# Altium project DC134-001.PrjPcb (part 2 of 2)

## Sheet DC134_USB.SchDoc
size 431 x 279 mm; Date: Not shown in title block; ApprovedBy: Not shown in title block; CheckedBy: Not shown in title block; Author: Not shown in title block; CompanyName: Not shown in title block; Engineer: Not shown in title block; Organization: Not shown in title block; Address1: Not shown in title block; Address2: Not shown in title block; Address3: Not shown in title block; Address4: Not shown in title block; DocumentNumber: 5; Revision: Use project parameter SCH_Rev; SheetNumber: 5; SheetTotal: 9; PageSetup: Record=PageOptions¦CenterHorizontal=True¦CenterVertical=True¦PrintScale=1.00¦XCorrection=1.00¦YCorrection=1.00¦PrintKind=0¦BorderSize=5000000¦LeftOffset=0¦BottomOffset=0¦Orientation=2¦PaperLength=1000¦PaperWidth=1000¦Scale=100¦PaperSource=15¦PrintQuality=600¦MediaType=1¦DitherType=10¦PaperKind=Letter¦PrintScaleMode=1
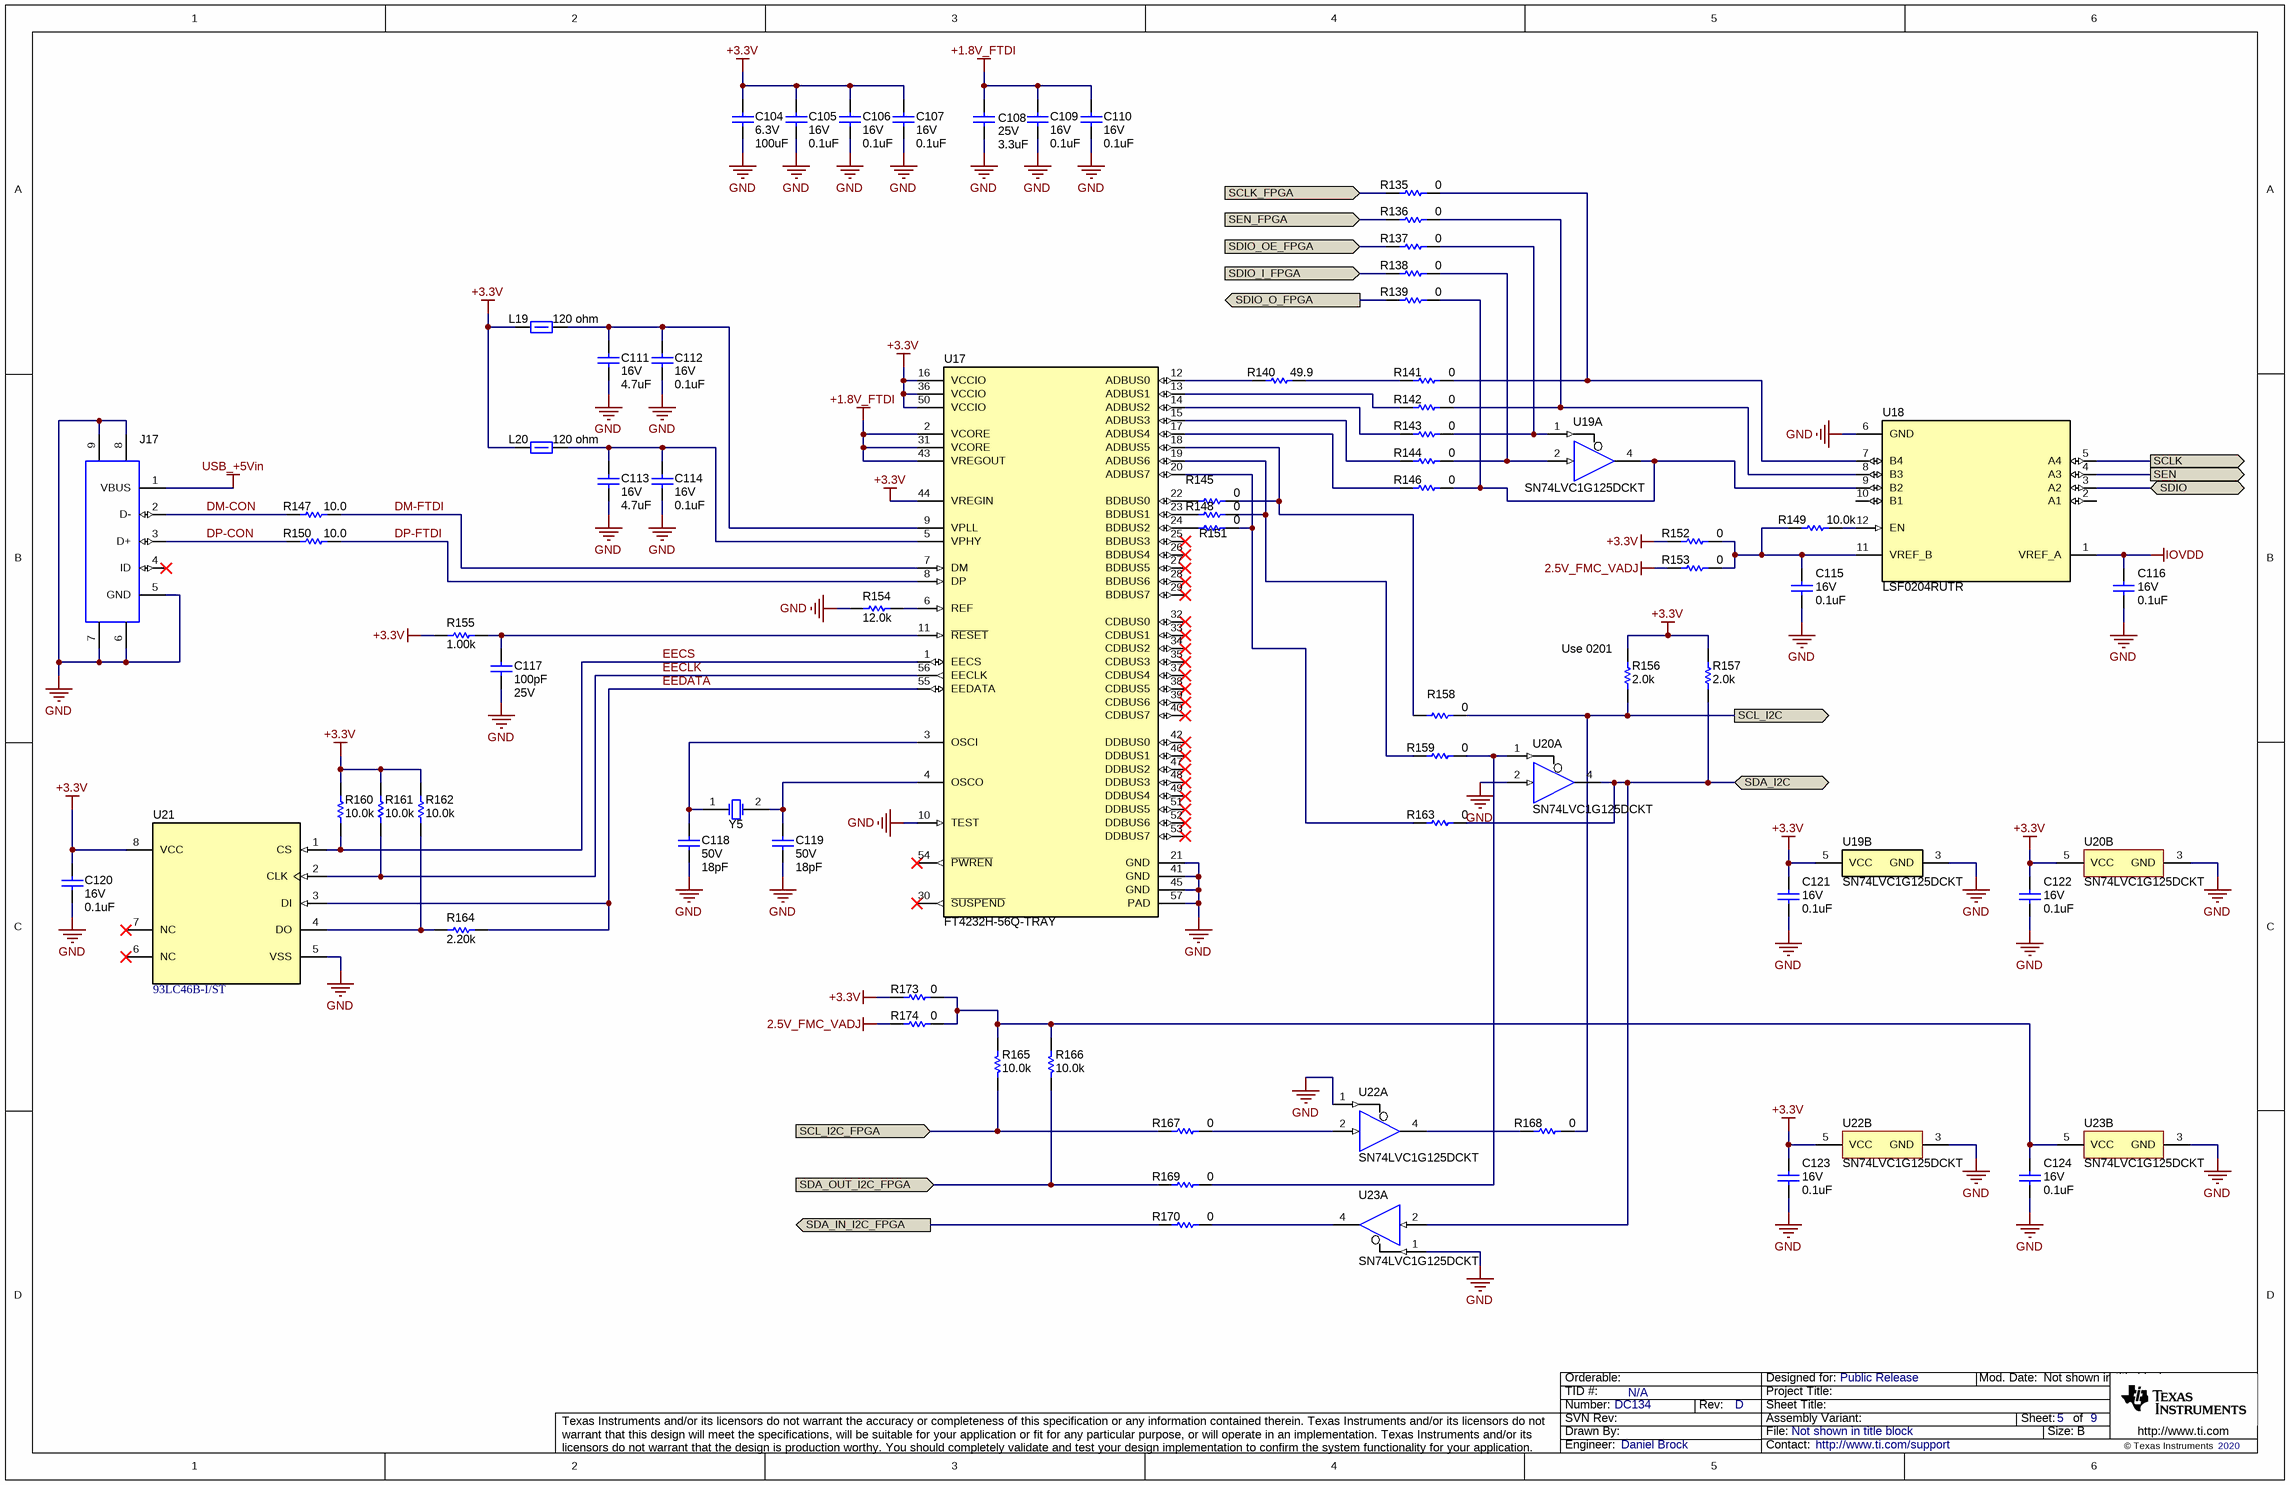
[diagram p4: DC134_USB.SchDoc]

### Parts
C104  VDC_V: 6.3V  ValueDisplayed: 100uF  [1206_190]  (hidden comment: C3216X5R0J107M160AB)
C105  VDC_V: 16V  ValueDisplayed: 0.1uF  [0201L]  (hidden comment: GRM033Z71C104KE14D)
C106  VDC_V: 16V  ValueDisplayed: 0.1uF  [0201L]  (hidden comment: GRM033Z71C104KE14D)
C107  VDC_V: 16V  ValueDisplayed: 0.1uF  [0201L]  (hidden comment: GRM033Z71C104KE14D)
C108  Value2: 25V  ValueDisplayed: 3.3uF  [0603]  (hidden comment: C1608X5R1E335K080AC)
C109  VDC_V: 16V  ValueDisplayed: 0.1uF  [0201L]  (hidden comment: GRM033Z71C104KE14D)
C110  VDC_V: 16V  ValueDisplayed: 0.1uF  [0201L]  (hidden comment: GRM033Z71C104KE14D)
C111  VDC_V: 16V  ValueDisplayed: 4.7uF  [0603]  (hidden comment: GRM188Z71C475KE21D)
C112  VDC_V: 16V  ValueDisplayed: 0.1uF  [0201L]  (hidden comment: GRM033Z71C104KE14D)
C113  VDC_V: 16V  ValueDisplayed: 4.7uF  [0603]  (hidden comment: GRM188Z71C475KE21D)
C114  VDC_V: 16V  ValueDisplayed: 0.1uF  [0201L]  (hidden comment: GRM033Z71C104KE14D)
C115  VDC_V: 16V  ValueDisplayed: 0.1uF  [0201L]  (hidden comment: GRM033Z71C104KE14D)
C116  VDC_V: 16V  ValueDisplayed: 0.1uF  [0201L]  (hidden comment: GRM033Z71C104KE14D)
C117  ValueDisplayed: 100pF  VDC_V: 25V  [0201L]  (hidden comment: CC0201JRNPO8BN101)
C118  VDC_V: 50V  ValueDisplayed: 18pF  [0402L]  (hidden comment: C1005C0G1H180J050BA)
C119  VDC_V: 50V  ValueDisplayed: 18pF  [0402L]  (hidden comment: C1005C0G1H180J050BA)
C120  VDC_V: 16V  ValueDisplayed: 0.1uF  [0201L]  (hidden comment: GRM033Z71C104KE14D)
C121  VDC_V: 16V  ValueDisplayed: 0.1uF  [0201L]  (hidden comment: GRM033Z71C104KE14D)
C122  VDC_V: 16V  ValueDisplayed: 0.1uF  [0201L]  (hidden comment: GRM033Z71C104KE14D)
C123  VDC_V: 16V  ValueDisplayed: 0.1uF  [0201L]  (hidden comment: GRM033Z71C104KE14D)
C124  VDC_V: 16V  ValueDisplayed: 0.1uF  [0201L]  (hidden comment: GRM033Z71C104KE14D)
J17  1734035-2  [CONN_USB-Mini-B-1734035-2]  (value not drawn)
L19  ValueDisplayed: 120 ohm  [0402]  (hidden comment: 74279271)
L20  ValueDisplayed: 120 ohm  [0402]  (hidden comment: 74279271)
R135  ValueDisplayed: 0  [0201L]  (hidden comment: CRCW02010000Z0ED)
R136  ValueDisplayed: 0  [0201L]  (hidden comment: CRCW02010000Z0ED)
R137  ValueDisplayed: 0  [0201L]  (hidden comment: CRCW02010000Z0ED)
R138  ValueDisplayed: 0  [0201L]  (hidden comment: CRCW02010000Z0ED)
R139  ValueDisplayed: 0  [0201L]  (hidden comment: CRCW02010000Z0ED)
R140  ValueDisplayed: 49.9  [0201L]  (hidden comment: RC0201FR-7D49R9L)
R141  ValueDisplayed: 0  [0201L]  (hidden comment: CRCW02010000Z0ED)
R142  ValueDisplayed: 0  [0201L]  (hidden comment: CRCW02010000Z0ED)
R143  ValueDisplayed: 0  [0201L]  (hidden comment: CRCW02010000Z0ED)
R144  ValueDisplayed: 0  [0201L]  (hidden comment: CRCW02010000Z0ED)
R145  ValueDisplayed: 0  [0201L]  (hidden comment: CRCW02010000Z0ED)
R146  ValueDisplayed: 0  [0201L]  (hidden comment: CRCW02010000Z0ED)
R147  ValueDisplayed: 10.0  [0402]  (hidden comment: RK73H1ETTP10R0F)
R148  ValueDisplayed: 0  [0201L]  (hidden comment: CRCW02010000Z0ED)
R149  ValueDisplayed: 10.0k  [0201L]  (hidden comment: RC0201FS-7D10KL)
R150  ValueDisplayed: 10.0  [0402]  (hidden comment: RK73H1ETTP10R0F)
R151  ValueDisplayed: 0  [0201L]  (hidden comment: CRCW02010000Z0ED)
R152  ValueDisplayed: 0  [0201L]  (hidden comment: CRCW02010000Z0ED)
R153  ValueDisplayed: 0  [0201L]  (hidden comment: CRCW02010000Z0ED)
R154  ValueDisplayed: 12.0k  [0201L]  (hidden comment: RC0201FR-7D12KL)
R155  ValueDisplayed: 1.00k  [0201L]  (hidden comment: RC0201FS-7D1KL)
R156  ValueDisplayed: 2.0k  [0402]  (hidden comment: CRCW04022K00JNED)
R157  ValueDisplayed: 2.0k  [0402]  (hidden comment: CRCW04022K00JNED)
R158  ValueDisplayed: 0  [0201L]  (hidden comment: CRCW02010000Z0ED)
R159  ValueDisplayed: 0  [0201L]  (hidden comment: CRCW02010000Z0ED)
R160  ValueDisplayed: 10.0k  [0201L]  (hidden comment: RC0201FR-7D10KL)
R161  ValueDisplayed: 10.0k  [0201L]  (hidden comment: RC0201FR-7D10KL)
R162  ValueDisplayed: 10.0k  [0201L]  (hidden comment: RC0201FR-7D10KL)
R163  ValueDisplayed: 0  [0201L]  (hidden comment: CRCW02010000Z0ED)
R164  ValueDisplayed: 2.20k  [0201L]  (hidden comment: RC0201FR-7D2K2L)
R165  ValueDisplayed: 10.0k  [0201L]  (hidden comment: RC0201FR-7D10KL)
R166  ValueDisplayed: 10.0k  [0201L]  (hidden comment: RC0201FR-7D10KL)
R167  ValueDisplayed: 0  [0201L]  (hidden comment: CRCW02010000Z0ED)
R168  ValueDisplayed: 0  [0201L]  (hidden comment: CRCW02010000Z0ED)
R169  ValueDisplayed: 0  [0201L]  (hidden comment: CRCW02010000Z0ED)
R170  ValueDisplayed: 0  [0201L]  (hidden comment: CRCW02010000Z0ED)
R173  ValueDisplayed: 0  [0402L]  (hidden comment: RC0402JR-070RL)
R174  ValueDisplayed: 0  [0402L]  (hidden comment: RC0402JR-070RL)
U17  FT4232H-56Q-TRAY  [VQFN-56]
U18  LSF0204RUTR  [RUT0012A]
U19  SN74LVC1G125DCKT  [DCK0005A_N]  (parts A,B of 2)
U20  SN74LVC1G125DCKT  [DCK0005A_N]  (parts A,B of 2)
U21  93LC46B-I/ST  [TSSOP-8]
U22  SN74LVC1G125DCKT  [DCK0005A_N]  (parts A,B of 2)
U23  SN74LVC1G125DCKT  [DCK0005A_N]  (parts A,B of 2)
Y5  ABM3-12.000MHZ-D2Y-T  [XTAL_ABM3]  (value not drawn)

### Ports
SCL_I2C (out), SCL_I2C_FPGA (in), SCLK (out), SCLK_FPGA (in), SDA_I2C (bidir), SDA_IN_I2C_FPGA (out), SDA_OUT_I2C_FPGA (in), SDIO (bidir), SDIO_I_FPGA (in), SDIO_O_FPGA (out), SDIO_OE_FPGA (in), SEN (out), SEN_FPGA (in)

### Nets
2.5V_FMC_VADJ: R153.1 R174.1
+1.8V_FTDI: C108.1 C109.2 C110.2 U17.2(VCORE) U17.31(VCORE) U17.43(VREGOUT)
+3.3V: C104.1 C105.2 C106.2 C107.2 C120.2 C121.1 C122.1 C123.1 L19.1 L20.1 R152.1 R155.1 R156.2 R157.2 R160.2 R161.2 R162.2 R173.1 U17.16(VCCIO) U17.36(VCCIO) U17.44(VREGIN) U17.50(VCCIO) U19.5(VCC) U20.5(VCC) U21.8(VCC) U22.5(VCC)
GND: C104.2 C105.1 C106.1 C107.1 C108.2 C109.1 C110.1 C111.2 C112.1 C113.2 C114.1 C115.2 C116.2 C117.2 C118.2 C119.2 C120.1 C121.2 C122.2 C123.2 C124.2 J17.5(GND) J17.6 J17.7 J17.8 J17.9 R154.1 U17.10(TEST) U17.21(GND) U17.41(GND) U17.45(GND) U17.57(PAD) U18.6(GND) U19.3(GND) U20.2(A) U20.3(GND) U21.5(VSS) U22.1(~{OE}) U22.3(GND) U23.1(~{OE}) U23.3(GND)
IOVDD: C116.1 U18.1(VREF_A)
USB_+5Vin: J17.1(VBUS)
DM-CON: J17.2(D-) R147.1
DM-FTDI: R147.2 U17.7(DM)
DP-CON: J17.3(D+) R150.1
DP-FTDI: R150.2 U17.8(DP)
EECLK: R161.1 U17.56(EECLK) U21.2(CLK)
EECS: R160.1 U17.1(EECS) U21.1(CS)
EEDATA: R164.2 U17.55(EEDATA) U21.3(DI)
SCL_I2C: R156.1 R158.2 R168.2 ; port SCL_I2C
SCL_I2C_FPGA: R165.2 R167.1 ; port SCL_I2C_FPGA
SCLK: U18.5(A4) ; port SCLK
SCLK_FPGA: R135.1 ; port SCLK_FPGA
SDA_I2C: R157.1 R163.2 U20.4(Y) U23.2(A) ; port SDA_I2C
SDA_IN_I2C_FPGA: R170.1 ; port SDA_IN_I2C_FPGA
SDA_OUT_I2C_FPGA: R166.2 R169.1 ; port SDA_OUT_I2C_FPGA
SDIO: U18.3(A2) ; port SDIO
SDIO_I_FPGA: R138.1 ; port SDIO_I_FPGA
SDIO_O_FPGA: R139.1 ; port SDIO_O_FPGA
SDIO_OE_FPGA: R137.1 ; port SDIO_OE_FPGA
SEN: U18.4(A3) ; port SEN
SEN_FPGA: R136.1 ; port SEN_FPGA
NetC111_1: C111.1 C112.2 L19.2 U17.9(VPLL)
NetC113_1: C113.1 C114.2 L20.2 U17.5(VPHY)
NetC115_1: C115.1 R149.2 R152.2 R153.2 U18.11(VREF_B)
NetC117_1: C117.1 R155.2 U17.11(~{RESET})
NetC118_1: C118.1 U17.3(OSCI) Y5.1(OSC1)
NetC119_1: C119.1 U17.4(OSCO) Y5.2(OSC2)
NetC124_1: C124.1 R165.1 R166.1 R173.2 R174.2 U23.5(VCC)
NetR135_2: R135.2 R141.2 U18.7(B4)
NetR136_2: R136.2 R142.2 U18.8(B3)
NetR137_2: R137.2 R143.2 U19.1(~{OE})
NetR138_2: R138.2 R144.2 U19.2(A)
NetR139_2: R139.2 R146.2 U18.9(B2) U19.4(Y)
NetR140_1: R140.1 U17.12(ADBUS0)
NetR140_2: R140.2 R141.1
NetR142_1: R142.1 U17.13(ADBUS1)
NetR143_1: R143.1 U17.14(ADBUS2)
NetR144_1: R144.1 U17.15(ADBUS3)
NetR145_1: R145.1 U17.22(BDBUS0)
NetR145_2: R145.2 R158.1 U17.18(ADBUS5)
NetR146_1: R146.1 U17.17(ADBUS4)
NetR148_1: R148.1 U17.23(BDBUS1)
NetR148_2: R148.2 R159.1 U17.19(ADBUS6)
NetR149_1: R149.1 U18.12(EN)
NetR151_1: R151.1 U17.24(BDBUS2)
NetR151_2: R151.2 R163.1 U17.20(ADBUS7)
NetR154_2: R154.2 U17.6(REF)
NetR159_2: R159.2 R169.2 U20.1(~{OE})
NetR162_1: R162.1 R164.1 U21.4(DO)
NetR167_2: R167.2 U22.2(A)
NetR168_1: R168.1 U22.4(Y)
NetR170_2: R170.2 U23.4(Y)

Not connected (* = marked no-connect by the designer): J17 4(ID)*; U17 25(BDBUS3)* 26(BDBUS4)* 27(BDBUS5)* 28(BDBUS6)* 29(BDBUS7)* 30(~{SUSPEND})* 32(CDBUS0)* 33(CDBUS1)* 34(CDBUS2)* 35(CDBUS3)* 37(CDBUS4)* 38(CDBUS5)* 39(CDBUS6)* 40(CDBUS7)* 42(DDBUS0)* 46(DDBUS1)* 47(DDBUS2)* 48(DDBUS3)* 49(DDBUS4)* 51(DDBUS5)* 52(DDBUS6)* 53(DDBUS7)* 54(~{PWREN})*; U18 2(A1) 10(B1); U21 6(NC)* 7(NC)*

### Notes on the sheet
- (near R156) Use 0201

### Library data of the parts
C104 = CMP-0064957-1: CAP, CERM, 100 uF, 6.3 V,+/- 20%, X5R, 1206; Manufacturer: TDK; TaMin_C: -55°C; Polarized: N; Green_Lifecycle: Active; SizeAreaWB_mm2: 10.92; Green_REACh: Passed; Value1: Unknown; U/M: EA; Value: 100uF; TaMax_C: 85°C; SizeZ_mm: 1.9; SizeX_mm: 3.2; SizeY_mm: 1.6; Cap_Case: 1206; SizeArea_mm2: 5.12; Cap_F: 100µF; AEC Category: Q200
C105-C107 C109 C110 C112 C114 C120 = CMP-0064970-1: CAP, CERM, 0.1 uF, 16 V,+/- 10%, X7R, 0201; Manufacturer: MuRata; TaMin_C: -55°C; Polarized: N; SizeAreaWB_mm2: 2.08; Value1: Unknown; U/M: EA; Value: 0.1uF; TaMax_C: 125°C; SizeZ_mm: 0.26; SizeX_mm: 0.6; SizeY_mm: 0.3; Cap_Case: 0201; SizeArea_mm2: 0.18; Cap_F: 100nF; AEC Category: Q200
C108 = CMP-0007008-5: CAP, CERM, 3.3 uF, 25 V, +/- 10%, X5R, 0603; Manufacturer: TDK; TaMin_C: -55°C; Polarized: N; SizeAreaWB_mm2: 4.68; Value1: Unknown; U/M: EA; Value: 3.3uF; TaMax_C: 85°C; SizeZ_mm: 1; SizeX_mm: 1.6; SizeY_mm: 0.8; SizeArea_mm2: 1.28; Cap_F: 3.3µF; AEC Category: Q200
C111 C113 = CMP-0064936-4: CAP, CERM, 4.7 uF, 16 V,+/- 10%, X7R, 0603; Manufacturer: MuRata; TaMin_C: -55°C; Polarized: N; SizeAreaWB_mm2: 4.68; Value1: Unknown; U/M: EA; Value: 4.7uF; TaMax_C: 125°C; SizeZ_mm: 1; SizeX_mm: 1.6; SizeY_mm: 0.8; SizeArea_mm2: 1.28; Cap_F: 4.7µF; AEC Category: Q200
C115 C116 C121-C124 = CMP-0064970-1: CAP, CERM, 0.1 uF, 16 V,+/- 10%, X7R, 0201; Manufacturer: MuRata; TaMin_C: -55°C; Polarized: N; SizeAreaWB_mm2: 2.08; Value1: Unknown; U/M: EA; Value: 0.1uF; TaMax_C: 125°C; SizeZ_mm: 0.26; SizeX_mm: 0.6; SizeY_mm: 0.3; Cap_Case: 0201; SizeArea_mm2: 0.18; CompType: Capacitor; Cap_F: 100nF; AEC Category: Q200
C117 = CMP-0085847-1: CAP, CERM, 100 pF, 25 V,+/- 5%, C0G/NP0, 0201; Manufacturer: Yageo; Polarized: N; Cap_Case: 0201; SizeX_mm: 0.6; TaMin_C: -55°C; AEC Category: Q200; SizeY_mm: 0.3; SizeZ_mm: 0.26; Value: 100pF; U/M: EA; SizeAreaWB_mm2: 2.08; TaMax_C: 125°C; SizeArea_mm2: 0.18
C118 C119 = CMP-0006247-2: CAP, CERM, 18 pF, 50 V, +/- 5%, C0G/NP0, 0402; Manufacturer: TDK; TaMin_C: -55°C; Polarized: N; SizeAreaWB_mm2: 3; Value1: Unknown; U/M: EA; Value: 18pF; TaMax_C: 125°C; SizeZ_mm: 0.6; SizeX_mm: 1; SizeY_mm: 0.5; Cap_Case: 0402; AEC Category: Q200
J17 = CMP-0054920-2: Connector, Receptacle, Mini-USB Type B, R/A, Top Mount SMT; Manufacturer: TE Connectivity; Green_Lifecycle: Active; Gender: Female; Green_REACh: Incomplete; CompType: USB
L19 L20 = CMP-0003214-1: Ferrite Bead, 120 ohm @ 100 MHz, 0.5 A, 0402; Manufacturer: Wurth Elektronik; Ztyp@1GHz_Ohm: 175.42; ZTyp@100MHz_Ohm: 120; SizeAreaWB_mm2: 3; DCR_ohm: 2d; Value1: 0.2 ohm; Value: 120 ohm; Imax_A: 5dA; SizeZ_mm: 0.6; SizeX_mm: 1; SizeY_mm: 0.5; Value2: 0.5A
R135-R139 R141-R146 R148 R151-R153 R158 R159 R163 R167-R170 = CMP-0027008-4: RES, 0, 5%, 0.05 W, 0201; Manufacturer: Vishay-Dale; Power_W: 50mW; TempCo: ppm/C; Value_Code: 0000; Value: 0; EIA_Code: E24; SizeX_mm: 0.6; SizeY_mm: 0.3; SizeZ_mm: 0.26; Value2: 0.05W; SizeArea_mm2: 0.18; CompType: Resistor; AEC Qualified: N; AEC Category: Q200
R140 = CMP-0028028-1: RES, 49.9, 1%, 0.05 W, 0201; Manufacturer: Yageo America; Power_W: 50mW; TempCo: 200 ppm/C; Value_Code: 49R9; U/M: EA; Value: 49.9; EIA_Code: E96; SizeX_mm: 0.6; SizeY_mm: 0.3; SizeZ_mm: 0.26; Value2: 0.05W; SizeArea_mm2: 0.18; AEC Qualified: N; VDC_V: 25V; AEC Category: Q200
R147 R150 = CMP-0026749-1: RES, 10.0, 1%, 0.063 W, 0402; Manufacturer: KOA Speer; Power_W: 63mW; TempCo: 100 ppm/C; Value_Code: 10R0; U/M: EA; Value: 10.0; EIA_Code: E96; Res_ohm: 10; SizeX_mm: 1; SizeY_mm: 0.5; SizeZ_mm: 0.6; Value2: 0.063W; AEC Qualified: N; VDC_V: 50V; AEC Category: Q200
R149 = CMP-0028071-1: RES, 10.0 k, 1%, 0.05 W, 0201; Manufacturer: Yageo America; Power_W: 50mW; TempCo: 200 ppm/C; Value_Code: 10k0; U/M: EA; Value: 10.0k; EIA_Code: E96; Res_ohm: 10k; SizeX_mm: 0.6; SizeY_mm: 0.3; SizeZ_mm: 0.26; Value2: 0.05W; SizeArea_mm2: 0.18; CompType: Resistor; AEC Qualified: N; VDC_V: 25V; AEC Category: Q200
R154 = CMP-0027954-1: RES, 12.0 k, 1%, 0.05 W, 0201; Manufacturer: Yageo America; Power_W: 50mW; TempCo: 200 ppm/C; Value_Code: 12k0; U/M: EA; Value: 12.0k; Res_ohm: 12k; SizeX_mm: 0.6; SizeY_mm: 0.3; SizeZ_mm: 0.26; Value2: 0.05W; SizeArea_mm2: 0.18; CompType: Resistor; AEC Qualified: N; VDC_V: 25V; AEC Category: Q200
R155 = CMP-0028084-1: RES, 1.00 k, 1%, 0.05 W, 0201; Manufacturer: Yageo America; Power_W: 50mW; TempCo: 200 ppm/C; Value_Code: 1k00; U/M: EA; Value: 1.00k; EIA_Code: E96; Res_ohm: 1k; SizeX_mm: 0.6; SizeY_mm: 0.3; SizeZ_mm: 0.26; Value2: 0.05W; SizeArea_mm2: 0.18; AEC Qualified: N; VDC_V: 25V; AEC Category: Q200
R156 R157 = CMP-0026889-5: RES, 2.0 k, 5%, 0.063 W, AEC-Q200 Grade 0, 0402; Manufacturer: Vishay-Dale; Power_W: 63mW; TempCo: 200 ppm/C; Value_Code: 2k00; Value: 2.0k; EIA_Code: E24; Res_ohm: 2k; SizeX_mm: 1; SizeY_mm: 0.5; SizeZ_mm: 0.6; Value2: 0.063W; AEC Qualified: Y; VDC_V: 50V; AEC Category: Q200; AEC Grade: 0
R160-R162 R165 = CMP-0027945-1: RES, 10.0 k, 1%, 0.05 W, 0201; Manufacturer: Yageo America; Power_W: 50mW; TempCo: 200 ppm/C; Value_Code: 10k0; U/M: EA; Value: 10.0k; EIA_Code: E96; Res_ohm: 10k; SizeX_mm: 0.6; SizeY_mm: 0.3; SizeZ_mm: 0.26; Value2: 0.05W; SizeArea_mm2: 0.18; AEC Qualified: N; VDC_V: 25V; AEC Category: Q200
R164 = CMP-0027995-1: RES, 2.20 k, 1%, 0.05 W, 0201; Manufacturer: Yageo America; Power_W: 50mW; TempCo: 200 ppm/C; Value_Code: 2k20; U/M: EA; Value: 2.20k; Res_ohm: 2.2k; SizeX_mm: 0.6; SizeY_mm: 0.3; SizeZ_mm: 0.26; Value2: 0.05W; SizeArea_mm2: 0.18; AEC Qualified: N; VDC_V: 25V; AEC Category: Q200
R166 = CMP-0027945-1: RES, 10.0 k, 1%, 0.05 W, 0201; Manufacturer: Yageo America; Power_W: 50mW; TempCo: 200 ppm/C; Value_Code: 10k0; U/M: EA; Value: 10.0k; EIA_Code: E96; Res_ohm: 10k; SizeX_mm: 0.6; SizeY_mm: 0.3; SizeZ_mm: 0.26; Value2: 0.05W; SizeArea_mm2: 0.18; CompType: Resistor; AEC Qualified: N; VDC_V: 25V; AEC Category: Q200
R173 R174 = CMP-0027004-2: RES, 0, 5%, 0.063 W, 0402; Manufacturer: Yageo America; Power_W: 63mW; TempCo: 200 ppm/C; Value_Code: 0000; U/M: EA; Value: 0; EIA_Code: E24; SizeX_mm: 1; SizeY_mm: 0.5; SizeZ_mm: 0.6; Value2: 0.063W; VDC_V: 50V; AEC Category: Q200
U17 = CMP-0081661-1: Future Technology Devices International Ltd FT4232H Quad High Speed USB to Multipurpose UART/MPSSE IC, VQFN-56; Manufacturer: FTDI; SizeZ_mm: 1; SizeX_mm: 8; SizeArea_mm2: 64; SizeAreaWB_mm2: 100
U18 = CMP-0066443-2: 4-Bit Bidirectional Multi-Voltage Level Translator for Open-Drain & Push- Pull, RUT0012A (UQFN-12); Manufacturer: Texas Instruments; SizeZ_mm: 0.55; SizeX_mm: 1.7; SizeY_mm: 2.0; SizeArea_mm2: 3.4; CompType: IC; U/M: EA; SizeAreaWB_mm2: 8.1
U19 = CMP-0051305-3: Single Bus Buffer Gate With 3-State Outputs, DCK0005A, SMALL T&R; Manufacturer: Texas Instruments; Output Type: CMOS; tpd @ Nom Voltage(Max)(ns): 9,5.5,4.5,4; VCC(Max)(V): 5.5; 3-State Output: Yes; VCC(Min)(V): 1.65; Input Type: CMOS/TTL; Rating: Catalog; Sub-Family: Non-Inverting Buffer/Driver; F @ Nom Voltage(Max)(Mhz): 150; Bits(#): 1; Schmitt Trigger: No; Voltage(Nom)(V): 1.8,2.5,3.3,5; Output Drive (IOL/IOH)(Max)(mA): 32/-32; Technology Family: LVC; ICC @ Nom Voltage(Max)(mA): 0.01; Logic: True; AEC Category: Q200; AEC Qualified: N; CompType: IC; SizeAreaWB_mm2: 9.3; SizeArea_mm2: 4.2; SizeX_mm: 2.1; SizeY_mm: 2.0; SizeZ_mm: 1.1
U20 U22 U23 = CMP-0051305-3: Single Bus Buffer Gate With 3-State Outputs, DCK0005A, SMALL T&R; Manufacturer: Texas Instruments; tpd @ Nom Voltage(Max)(ns): 9,5.5,4.5,4; Output Drive (IOL/IOH)(Max)(mA): 32/-32; Voltage(Nom)(V): 1.8,2.5,3.3,5; Bits(#): 1; Rating: Catalog; Output Type: CMOS; Technology Family: LVC; 3-State Output: Yes; Sub-Family: Non-Inverting Buffer/Driver; Logic: True; Input Type: CMOS/TTL; Schmitt Trigger: No; VCC(Min)(V): 1.65; VCC(Max)(V): 5.5; ICC @ Nom Voltage(Max)(mA): 0.01; F @ Nom Voltage(Max)(Mhz): 150; AEC Category: Q200; AEC Qualified: N; CompType: IC; SizeAreaWB_mm2: 9.3; SizeArea_mm2: 4.2; SizeX_mm: 2.1; SizeY_mm: 2.0; SizeZ_mm: 1.1
U21 = CMP-0081524-1: 1K Microwire Compatible Serial EEPROM, TSSOP-8; Manufacturer: Microchip; SizeArea_mm2: 19.2; SizeAreaWB_mm2: 42; SizeY_mm: 3; SizeZ_mm: 1.2; SizeX_mm: 6.4
Y5 = CMP-0004616-3: Crystal, 12 MHz, 18 pF, SMD; Manufacturer: Abracon Corporation; TaMin_C: -40°C; Frequency Stability: +/-30ppm; Frequency_Fixed: 12MHz; TaMax_C: 85°C

## Sheet DC134_Power.SchDoc: Power-Supply_Buffer
size 431 x 279 mm; Date: Not shown in title block; ApprovedBy: Not shown in title block; CheckedBy: Not shown in title block; Author: Not shown in title block; CompanyName: Not shown in title block; DrawnBy: Daniel Brock; Engineer: Not shown in title block; Organization: Not shown in title block; Address1: Not shown in title block; Address2: Not shown in title block; Address3: Not shown in title block; Address4: Not shown in title block; DocumentNumber: 6; Revision: Use project parameter SCH_Rev; SheetNumber: 6; SheetTotal: 9; PageSetup: Record=PageOptions¦CenterHorizontal=True¦CenterVertical=True¦PrintScale=1.00¦XCorrection=1.00¦YCorrection=1.00¦PrintKind=0¦BorderSize=5000000¦LeftOffset=0¦BottomOffset=0¦Orientation=2¦PaperLength=1000¦PaperWidth=1000¦Scale=100¦PaperSource=15¦PrintQuality=600¦MediaType=1¦DitherType=10¦PaperKind=Letter¦PrintScaleMode=1
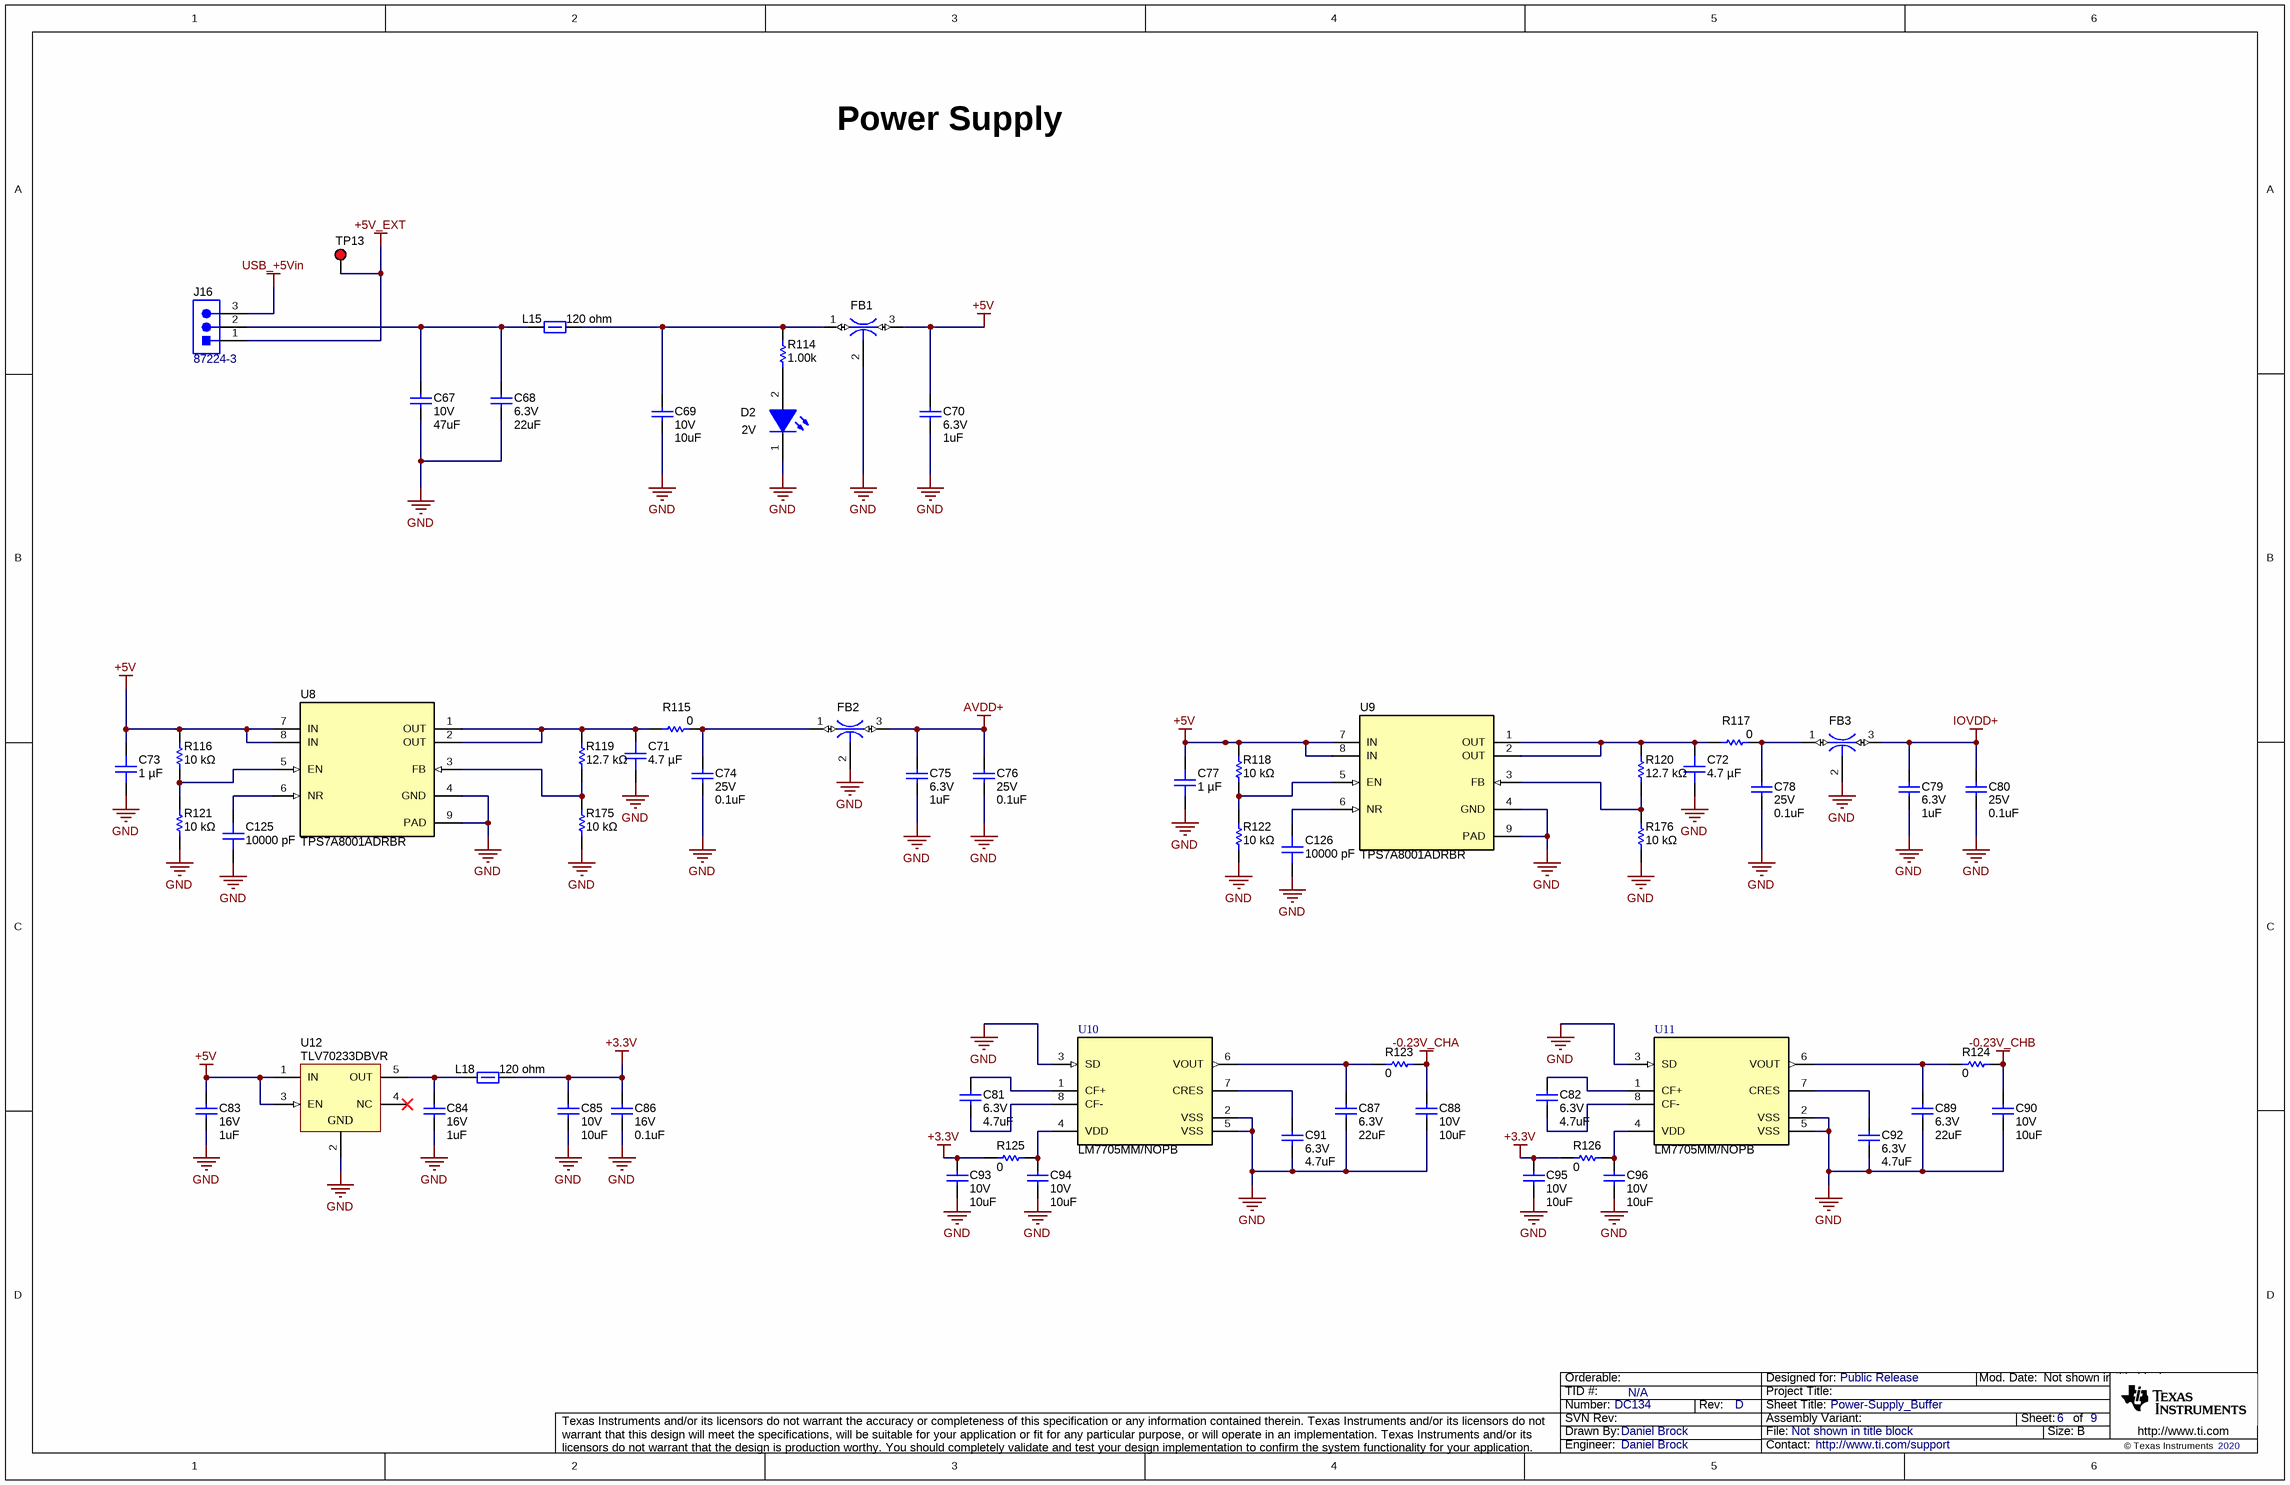
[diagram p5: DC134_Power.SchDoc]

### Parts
C67  VDC_V: 10V  ValueDisplayed: 47uF  [1210_270]  (hidden comment: GRM32ER61A476KE20L)
C68  VDC_V: 6.3V  ValueDisplayed: 22uF  [0805_HV]  (hidden comment: JMK212BJ226MG-T)
C69  VDC_V: 10V  ValueDisplayed: 10uF  [0603]  (hidden comment: GRM188R61A106ME69D)
C70  VDC_V: 6.3V  ValueDisplayed: 1uF  [0402]  (hidden comment: GRM152R60J105ME15D)
C71  value 4.7 µF  [0402L]  (hidden comment: C1005X5R1A475K050BC)
C72  value 4.7 µF  [0402L]  (hidden comment: C1005X5R1A475K050BC)
C73  value 1 µF  [0402L]  (hidden comment: C1005X6S1A105K050BC)
C74  VDC_V: 25V  ValueDisplayed: 0.1uF  [0201_033]  (hidden comment: GRM033R61E104KE14J)
C75  VDC_V: 6.3V  ValueDisplayed: 1uF  [0402]  (hidden comment: GRM152R60J105ME15D)
C76  VDC_V: 25V  ValueDisplayed: 0.1uF  [0201_033]  (hidden comment: GRM033R61E104KE14J)
C77  value 1 µF  [0402L]  (hidden comment: C1005X6S1A105K050BC)
C78  VDC_V: 25V  ValueDisplayed: 0.1uF  [0201_033]  (hidden comment: GRM033R61E104KE14J)
C79  VDC_V: 6.3V  ValueDisplayed: 1uF  [0402]  (hidden comment: GRM152R60J105ME15D)
C80  VDC_V: 25V  ValueDisplayed: 0.1uF  [0201_033]  (hidden comment: GRM033R61E104KE14J)
C81  VDC_V: 6.3V  ValueDisplayed: 4.7uF  [0603]  (hidden comment: GRM188R60J475KE19D)
C82  VDC_V: 6.3V  ValueDisplayed: 4.7uF  [0603]  (hidden comment: GRM188R60J475KE19D)
C83  VDC_V: 16V  ValueDisplayed: 1uF  [0603]  (hidden comment: 885012206052)
C84  VDC_V: 16V  ValueDisplayed: 1uF  [0603]  (hidden comment: 885012206052)
C85  VDC_V: 10V  ValueDisplayed: 10uF  [0805_HV]  (hidden comment: 885012207026)
C86  VDC_V: 16V  ValueDisplayed: 0.1uF  [0201L]  (hidden comment: GRM033Z71C104KE14D)
C87  VDC_V: 6.3V  ValueDisplayed: 22uF  [0805_HV]  (hidden comment: JMK212BJ226MG-T)
C88  VDC_V: 10V  ValueDisplayed: 10uF  [0805_HV]  (hidden comment: 885012207026)
C89  VDC_V: 6.3V  ValueDisplayed: 22uF  [0805_HV]  (hidden comment: JMK212BJ226MG-T)
C90  VDC_V: 10V  ValueDisplayed: 10uF  [0805_HV]  (hidden comment: 885012207026)
C91  VDC_V: 6.3V  ValueDisplayed: 4.7uF  [0603]  (hidden comment: GRM188R60J475KE19D)
C92  VDC_V: 6.3V  ValueDisplayed: 4.7uF  [0603]  (hidden comment: GRM188R60J475KE19D)
C93  VDC_V: 10V  ValueDisplayed: 10uF  [0805_HV]  (hidden comment: 885012207026)
C94  VDC_V: 10V  ValueDisplayed: 10uF  [0805_HV]  (hidden comment: 885012207026)
C95  VDC_V: 10V  ValueDisplayed: 10uF  [0805_HV]  (hidden comment: 885012207026)
C96  VDC_V: 10V  ValueDisplayed: 10uF  [0805_HV]  (hidden comment: 885012207026)
C125  value 10000 pF  [0402L]  (hidden comment: 0402ZC103JAT2A)
C126  value 10000 pF  [0402L]  (hidden comment: 0402ZC103JAT2A)
D2  Value2: 2V  [LTST-C150_1206_Green]  (hidden comment: LTST-C150KGKT)
FB1  NFM31PC276B0J3L  [Murata_NFM31P]  (value not drawn)
FB2  NFM31PC276B0J3L  [Murata_NFM31P]  (value not drawn)
FB3  NFM31PC276B0J3L  [Murata_NFM31P]  (value not drawn)
J16  87224-3  [TE_87224-3]
L15  ValueDisplayed: 120 ohm  [0402]  (hidden comment: 74279271)
L18  ValueDisplayed: 120 ohm  [0402]  (hidden comment: 74279271)
R114  ValueDisplayed: 1.00k  [0402]  (hidden comment: RC0402FR-071KL)
R115  value 0  [0402]  (hidden comment: Resistor)
R116  value 10 kΩ  [0402L]  (hidden comment: ERJ-2RKF1002X)
R117  value 0  [0402]  (hidden comment: Resistor)
R118  value 10 kΩ  [0402L]  (hidden comment: ERJ-2RKF1002X)
R119  value 12.7 kΩ  [0402L]  (hidden comment: ERJ-2RKF1272X)
R120  value 12.7 kΩ  [0402L]  (hidden comment: ERJ-2RKF1272X)
R121  value 10 kΩ  [0402L]  (hidden comment: ERJ-2RKF1002X)
R122  value 10 kΩ  [0402L]  (hidden comment: ERJ-2RKF1002X)
R123  ValueDisplayed: 0  [0402]  (hidden comment: RK73Z1ETTP)
R124  ValueDisplayed: 0  [0402]  (hidden comment: RK73Z1ETTP)
R125  ValueDisplayed: 0  [0402]  (hidden comment: RK73Z1ETTP)
R126  ValueDisplayed: 0  [0402]  (hidden comment: RK73Z1ETTP)
R175  value 10 kΩ  [0402L]  (hidden comment: ERJ-2RKF1002X)
R176  value 10 kΩ  [0402L]  (hidden comment: ERJ-2RKF1002X)
TP13  5010  [Keystone5010]  (value not drawn)
U8  TPS7A8001ADRBR  [DRB0008A]
U9  TPS7A8001ADRBR  [DRB0008A]
U10  LM7705MM/NOPB  [DGK0008A_N]
U11  LM7705MM/NOPB  [DGK0008A_N]
U12  TLV70233DBVR  [DBV0005A_N]

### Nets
+3.3V: C85.1 C86.2 C93.1 C95.1 L18.2 R125.1 R126.1
+5V: C70.1 C73.2 C77.2 C83.1 FB1.3 R116.2 R118.2 U8.7(IN) U8.8(IN) U9.7(IN) U9.8(IN) U12.1(IN) U12.3(EN)
+5V_EXT: J16.1 TP13.1
-0.23V_CHA: C88.1 R123.2
-0.23V_CHB: C90.1 R124.2
AVDD+: C75.1 C76.1 FB2.3
GND: C67.2 C68.2 C69.2 C70.2 C71.1 C72.1 C73.1 C74.2 C75.2 C76.2 C77.1 C78.2 C79.2 C80.2 C83.2 C84.2 C85.2 C86.1 C87.2 C88.2 C89.2 C90.2 C91.2 C92.2 C93.2 C94.2 C95.2 C96.2 C125.1 C126.1 D2.1(K) FB1.2 FB2.2 FB3.2 R121.1 R122.1 R175.1 R176.1 U8.4(GND) U8.9(PAD) U9.4(GND) U9.9(PAD) U10.2(VSS) U10.3(SD) U10.5(VSS) U11.2(VSS) U11.3(SD) U11.5(VSS) U12.2(GND)
IOVDD+: C79.1 C80.1 FB3.3
USB_+5Vin: J16.3
NetC67_1: C67.1 C68.1 J16.2 L15.1
NetC69_1: C69.1 FB1.1 L15.2 R114.2
NetC71_2: C71.2 R115.1 R119.2 U8.1(OUT) U8.2(OUT)
NetC72_2: C72.2 R117.1 R120.2 U9.1(OUT) U9.2(OUT)
NetC74_1: C74.1 FB2.1 R115.2
NetC78_1: C78.1 FB3.1 R117.2
NetC81_1: C81.1 U10.1(CF+)
NetC81_2: C81.2 U10.8(CF-)
NetC82_1: C82.1 U11.1(CF+)
NetC82_2: C82.2 U11.8(CF-)
NetC84_1: C84.1 L18.1 U12.5(OUT)
NetC87_1: C87.1 R123.1 U10.6(VOUT)
NetC89_1: C89.1 R124.1 U11.6(VOUT)
NetC91_1: C91.1 U10.7(CRES)
NetC92_1: C92.1 U11.7(CRES)
NetC94_1: C94.1 R125.2 U10.4(VDD)
NetC96_1: C96.1 R126.2 U11.4(VDD)
NetC125_2: C125.2 U8.6(NR)
NetC126_2: C126.2 U9.6(NR)
NetD2_2: D2.2(A) R114.1
NetR116_1: R116.1 R121.2 U8.5(EN)
NetR118_1: R118.1 R122.2 U9.5(EN)
NetR119_1: R119.1 R175.2 U8.3(FB)
NetR120_1: R120.1 R176.2 U9.3(FB)

Not connected (* = marked no-connect by the designer): U12 4(NC)*

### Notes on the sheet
- Power Supply

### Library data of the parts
C67 = CMP-0009208-2: CAP, CERM, 47 uF, 10 V, +/- 10%, X5R, 1210; Manufacturer: MuRata; TaMin_C: -55°C; ESR_ohm: 1m; Polarized: N; SizeAreaWB_mm2: 14.7; Value1: 0.001 ohm; U/M: EA; Value: 47uF; TaMax_C: 85°C; SizeZ_mm: 2.7; SizeX_mm: 3.2; SizeY_mm: 2.5; Cap_Case: 1210; SizeArea_mm2: 8; Cap_F: 47µF; AEC Category: Q200
C68 C87 C89 = CMP-0008391-2: CAP, CERM, 22 uF, 6.3 V, +/- 20%, X5R, 0805; Manufacturer: Taiyo Yuden; TaMin_C: -55°C; Polarized: N; SizeAreaWB_mm2: 6.75; Value1: Unknown; U/M: EA; Value: 22uF; TaMax_C: 85°C; SizeZ_mm: 1.45; SizeX_mm: 2; SizeY_mm: 1.25; Cap_Case: 0805; SizeArea_mm2: 2.5; Cap_F: 22µF; AEC Category: Q200
C69 = CMP-0007318-5: CAP, CERM, 10 uF, 10 V, +/- 20%, X5R, 0603; Manufacturer: MuRata; TaMin_C: -55°C; Polarized: N; SizeAreaWB_mm2: 4.68; Value1: Unknown; U/M: EA; Value: 10uF; TaMax_C: 85°C; SizeZ_mm: 1; SizeX_mm: 1.6; SizeY_mm: 0.8; SizeArea_mm2: 1.28; Cap_F: 10µF; AEC Category: Q200
C70 C75 C79 = CMP-0006372-2: CAP, CERM, 1 uF, 6.3 V, +/- 20%, X5R, 0402; Manufacturer: MuRata; TaMin_C: -55°C; Polarized: N; SizeAreaWB_mm2: 3; Value1: Unknown; U/M: EA; Value: 1uF; TaMax_C: 85°C; SizeZ_mm: 0.6; SizeX_mm: 1; SizeY_mm: 0.5; Cap_F: 1µF; AEC Category: Q200
C71 C72 = capcc03298: CAP CER 4.7UF 10V X5R 0402; Manufacturer: TDK Corporation; Tolerance: ±10%; SizeX_mm: 1; SizeY_mm: 0.5; SizeZ_mm: 0.65
C73 C77 = capcc02726: CAP CER 1UF 10V X6S 0402; Manufacturer: TDK Corporation; Tolerance: ±10%; SizeX_mm: 1; SizeY_mm: 0.5; SizeZ_mm: 0.55
C74 C76 C78 C80 = CMP-0009719-2: CAP, CERM, 0.1 uF, 25 V, +/- 10%, X5R, 0201; Manufacturer: MuRata; TaMin_C: -55°C; Polarized: N; SizeAreaWB_mm2: 2.08; Value1: Unknown; U/M: EA; Value: 0.1uF; TaMax_C: 85°C; SizeZ_mm: 0.33; SizeX_mm: 0.6; SizeY_mm: 0.3; Cap_Case: 0201; SizeArea_mm2: 0.18; Cap_F: 100nF; AEC Category: Q200
C81 C82 C91 C92 = CMP-0007311-5: CAP, CERM, 4.7 uF, 6.3 V, +/- 10%, X5R, 0603; Manufacturer: MuRata; TaMin_C: -55°C; ESR_ohm: 5m; Polarized: N; SizeAreaWB_mm2: 4.68; Value1: 0.005 ohm; U/M: EA; Value: 4.7uF; TaMax_C: 85°C; SizeZ_mm: 1; SizeX_mm: 1.6; SizeY_mm: 0.8; SizeArea_mm2: 1.28; Cap_F: 4.7µF; IRMS_A: 2A; AEC Category: Q200
C83 C84 = CMP-0006831-4: CAP, CERM, 1 uF, 16 V, +/- 10%, X7R, 0603; Manufacturer: Wurth Elektronik; TaMin_C: -55°C; Polarized: N; SizeAreaWB_mm2: 4.68; Value1: Unknown; U/M: EA; Value: 1uF; TaMax_C: 125°C; SizeZ_mm: 1; SizeX_mm: 1.6; SizeY_mm: 0.8; SizeArea_mm2: 1.28; Cap_F: 1µF; AEC Category: Q200
C85 C88 C90 C93-C96 = CMP-0007691-2: CAP, CERM, 10 uF, 10 V, +/- 10%, X7R, 0805; Manufacturer: Wurth Elektronik; TaMin_C: -55°C; Polarized: N; SizeAreaWB_mm2: 6.75; Value1: Unknown; U/M: EA; Value: 10uF; TaMax_C: 125°C; SizeZ_mm: 1.45; SizeX_mm: 2; SizeY_mm: 1.25; Cap_Case: 0805; SizeArea_mm2: 2.5; Cap_F: 10µF; AEC Category: Q200
C86 = CMP-0064970-1: as C105 on sheet DC134_USB
C125 C126 = capcc05563: CAP CER 10000PF 10V X7R 0402; Manufacturer: KYOCERA AVX; Tolerance: ±5%; SizeX_mm: 1; SizeY_mm: 0.5; SizeZ_mm: 0.56
D2 = CMP-0002920-2: LED, Green, SMD; Manufacturer: LiteOn; Io_A: 30mA; Vr_V: 5V; Tjmax_C: 85°C; Value1: W; Angle: 130; Type: AlInGaP
FB1-FB3 = CMP-0001934-2: FILTER LC HIGH FREQ 27uF 1206; Manufacturer: MuRata
J16 = CMP-0078139-1: Header, 2.54mm, 3x1, Gold, TH; Manufacturer: TE Connectivity; Pitch_mm: 2.54; Gender: Male; Cert_UL: Y; Current_A: 3A; Voltage_V: 750V; Green_REACh: Passed; Shrouded: N; Green_Lifecycle: Active; Row_Count: 1
L15 L18 = CMP-0003214-1: as L19 on sheet DC134_USB
R114 = CMP-0026725-1: RES, 1.00 k, 1%, 0.0625 W, 0402; Manufacturer: Yageo America; Power_W: 62.5mW; TempCo: 100 ppm/C; Value_Code: 1k00; U/M: EA; Value: 1.00k; EIA_Code: E96; Res_ohm: 1k; SizeX_mm: 1; SizeY_mm: 0.5; SizeZ_mm: 0.6; AEC Qualified: N; VDC_V: 50V; AEC Category: Q200
R115 R117 = CMP-0026822-3: RES, 0, 5%, 0.063 W, AEC-Q200 Grade 0, 0402; Manufacturer: Vishay-Dale; PartNumber: CRCW04020000Z0ED; Value_Code: 0000; Power_W: 63mW; Value2: 0.063W; VDC_V: 50V; TempCo: 200 ppm/C; EIA_Code: E24; AEC Category: Q200; AEC Qualified: Y; SizeArea_mm2: 0.5; SizeX_mm: 1; SizeZ_mm: 0.6
R116 R118 R121 R122 R175 R176 = RSMD040201951: RES SMD 10K OHM 1% 1/10W 0402; Manufacturer: Panasonic Electronic Components; Power (Watts): 0.1W, 1/10W; Temperature Coefficient: ±100ppm/°C; SizeX_mm: 1; SizeY_mm: 0.5; SizeZ_mm: 0.4
R119 R120 = RSMD040202026: RES SMD 12.7K OHM 1% 1/10W 0402; Manufacturer: Panasonic Electronic Components; Power (Watts): 0.1W, 1/10W; Temperature Coefficient: ±100ppm/°C; SizeX_mm: 1; SizeY_mm: 0.5; SizeZ_mm: 0.4
R123-R126 = CMP-0027007-2: RES, 0, 5%, 0.063 W, AEC-Q200 Grade 0, 0402; Manufacturer: KOA Speer; Power_W: 63mW; TempCo: ppm/C; Value_Code: 0000; U/M: EA; Value: 0; EIA_Code: E24; SizeX_mm: 1; SizeY_mm: 0.5; SizeZ_mm: 0.6; Value2: 0.063W; AEC Qualified: Y; AEC Category: Q200
TP13 = CMP-0055147-2: Test Point, Multipurpose, Red, TH; Manufacturer: Keystone Electronics; CT: TRUE; ContactFinish: Silver; Green_Lifecycle: Active; CNHeader: FALSE; Green_REACh: Passed
U8 U9 = CMP-0065176-4: #N/A; Alternate PartNumber: TPS7A8001ADRBT; Alternate Manufacturer: Texas Instruments; SizeZ_mm: 1.0; SizeArea_mm2: 9.0; AEC Qualified: N; CompType: IC; SizeAreaWB_mm2: 16.0; SizeY_mm: 3.0; AEC Category: Q200
U10 U11 = CMP-0072065-2: Low Noise Negative Bias Generator, 8-pin Mini SOIC, Pb-Free; Manufacturer: Texas Instruments; CompType: IC; PowerWise: N
U12 = CMP-0035516-1: Single Output LDO, 300 mA, Fixed 3.3 V Output, 2 to 5.5 V Input, with Low IQ, 5-pin SOT-23 (DBV), -40 to 125 degC, Green (RoHS & no Sb/Br); Manufacturer: Texas Instruments; Fixed Output Options(V): 3.3; Vdo(Typ)(mV): 220; Accuracy(%): 2; Iq(Typ)(mA): 0.03; SubFamily: Single Channel LDO; Iout(Max)(A): 0.3; Vin(Max)(V): 5.5

## Sheet DC134_Reference.SchDoc
size 431 x 279 mm; Date: Not shown in title block; ApprovedBy: Not shown in title block; CheckedBy: Not shown in title block; Author: Not shown in title block; CompanyName: Not shown in title block; Engineer: Not shown in title block; Organization: Not shown in title block; Address1: Not shown in title block; Address2: Not shown in title block; Address3: Not shown in title block; Address4: Not shown in title block; DocumentNumber: 7; Revision: Use project parameter SCH_Rev; SheetNumber: 7; SheetTotal: 9; PageSetup: Record=PageOptions¦CenterHorizontal=True¦CenterVertical=True¦PrintScale=1.00¦XCorrection=1.00¦YCorrection=1.00¦PrintKind=0¦BorderSize=5000000¦LeftOffset=0¦BottomOffset=0¦Orientation=2¦PaperLength=1000¦PaperWidth=1000¦Scale=100¦PaperSource=15¦PrintQuality=600¦MediaType=1¦DitherType=10¦PaperKind=Letter¦PrintScaleMode=1
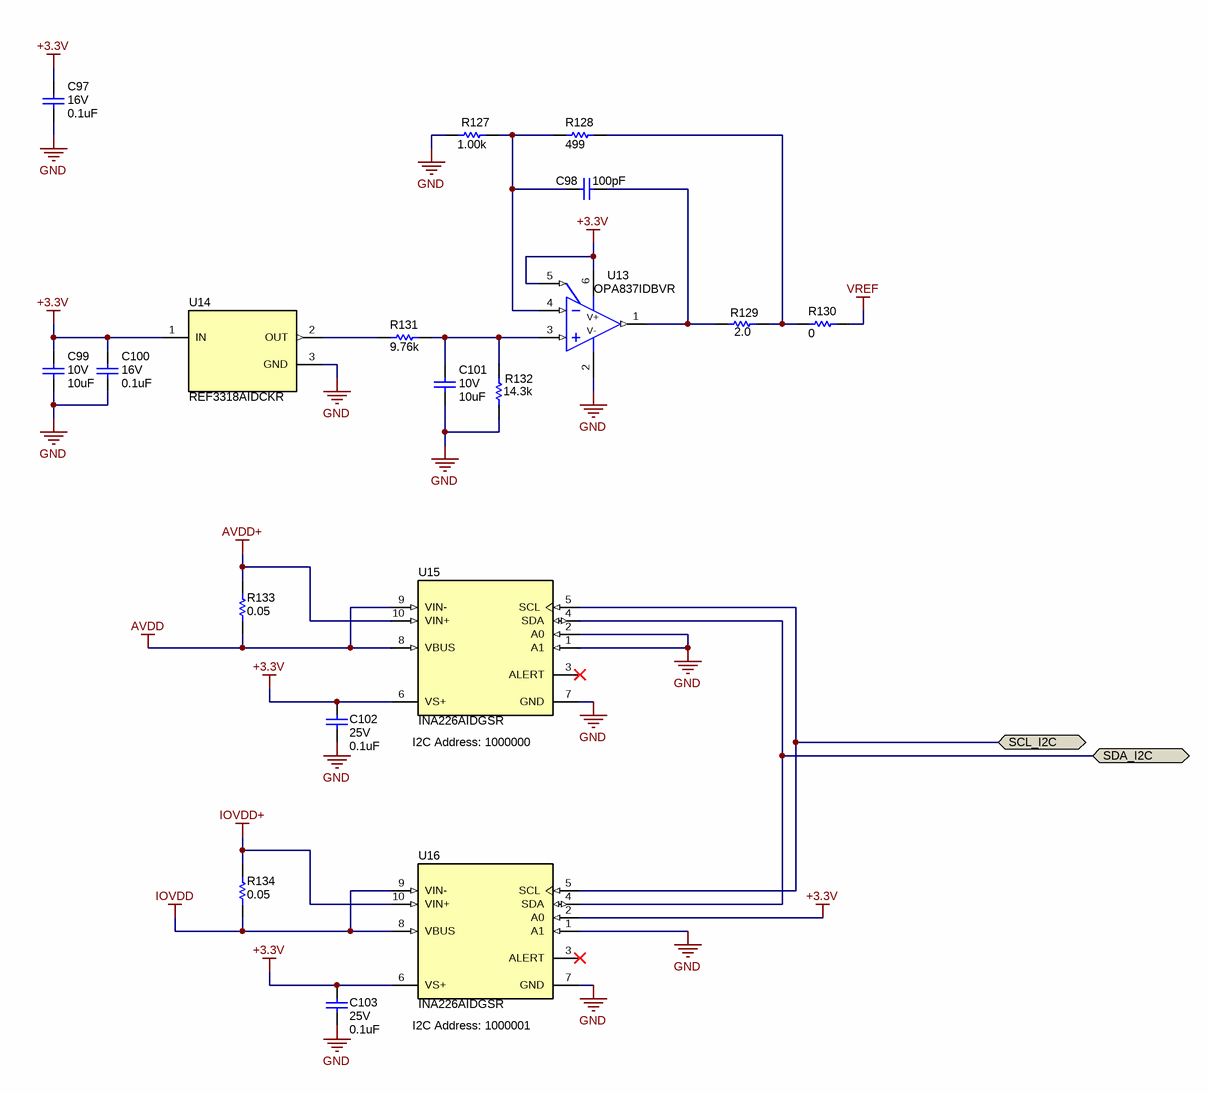
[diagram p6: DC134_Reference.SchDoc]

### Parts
C97  VDC_V: 16V  ValueDisplayed: 0.1uF  [0201L]  (hidden comment: GRM033Z71C104KE14D)
C98  ValueDisplayed: 100pF  [0201_033L]  (hidden comment: GRM033R71E101JA01D)
C99  VDC_V: 10V  ValueDisplayed: 10uF  [0603L]  (hidden comment: GRM188Z71A106MA73D)
C100  VDC_V: 16V  ValueDisplayed: 0.1uF  [0201L]  (hidden comment: GRM033Z71C104KE14D)
C101  VDC_V: 10V  ValueDisplayed: 10uF  [0603L]  (hidden comment: GRM188Z71A106MA73D)
C102  VDC_V: 25V  ValueDisplayed: 0.1uF  [0402]  (hidden comment: GRM155R61E104KA87D)
C103  VDC_V: 25V  ValueDisplayed: 0.1uF  [0402]  (hidden comment: GRM155R61E104KA87D)
R127  ValueDisplayed: 1.00k  [0201L]  (hidden comment: RC0201FR-071KL)
R128  ValueDisplayed: 499  [0201L]  (hidden comment: RC0201FR-07499RL)
R129  ValueDisplayed: 2.0  [0201L]  (hidden comment: RC0201JR-072RL)
R130  ValueDisplayed: 0  [0201L]  (hidden comment: CRCW02010000Z0ED)
R131  ValueDisplayed: 9.76k  [0201L]  (hidden comment: RC0201FR-079K76L)
R132  ValueDisplayed: 14.3k  [0201L]  (hidden comment: RC0201FR-0714K3L)
R133  ValueDisplayed: 0.05  [0603]  (hidden comment: ERJ-L03KF50MV)
R134  ValueDisplayed: 0.05  [0603]  (hidden comment: ERJ-L03KF50MV)
U13  OPA837IDBVR  [DBV0006A_N]
U14  REF3318AIDCKR  [DCK0003A_N]
U15  INA226AIDGSR  [DGS0010A_L]
U16  INA226AIDGSR  [DGS0010A_L]

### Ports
SCL_I2C (bidir), SDA_I2C (bidir)

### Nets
+3.3V: C97.1 C99.1 C100.1 C102.1 C103.1 U13.5(PD) U13.6(V+) U14.1(IN) U15.6(VS+) U16.2(A0) U16.6(VS+)
AVDD: R133.1 U15.8(VBUS) U15.9(VIN-)
AVDD+: R133.2 U15.10(VIN+)
GND: C97.2 C99.2 C100.2 C101.2 C102.2 C103.2 R127.1 R132.1 U13.2(V-) U14.3(GND) U15.1(A1) U15.2(A0) U15.7(GND) U16.1(A1) U16.7(GND)
IOVDD: R134.1 U16.8(VBUS) U16.9(VIN-)
IOVDD+: R134.2 U16.10(VIN+)
VREF: R130.2
SCL_I2C: U15.5(SCL) U16.5(SCL) ; port SCL_I2C
SDA_I2C: U15.4(SDA) U16.4(SDA) ; port SDA_I2C
NetC98_1: C98.1 R129.1 U13.1(OUT)
NetC98_2: C98.2 R127.2 R128.1 U13.4(IN-)
NetC101_1: C101.1 R131.2 R132.2 U13.3(IN+)
NetR128_2: R128.2 R129.2 R130.1
NetR131_1: R131.1 U14.2(OUT)

Not connected (* = marked no-connect by the designer): U15 3(ALERT)*; U16 3(ALERT)*

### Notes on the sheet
- (near U15) I2C Address: 1000000
- (near U16) I2C Address: 1000001

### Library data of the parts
C97 C100 = CMP-0064970-1: as C115 on sheet DC134_USB
C98 = CMP-0009762-1: CAP, CERM, 100 pF, 25 V, +/- 5%, C0G/NP0, 0201; Manufacturer: MuRata; TaMin_C: -55°C; Polarized: N; SizeAreaWB_mm2: 2.08; Value1: Unknown; U/M: EA; Value: 100pF; TaMax_C: 125°C; SizeZ_mm: 0.33; SizeX_mm: 0.6; SizeY_mm: 0.3; Cap_Case: 0201; Value2: 25V; SizeArea_mm2: 0.18; CompType: Capacitor; AEC Category: Q200
C99 C101 = CMP-0007497-5: CAP, CERM, 10 uF, 10 V, +/- 20%, X7R, 0603; Manufacturer: MuRata; TaMin_C: -55°C; Polarized: N; SizeAreaWB_mm2: 4.68; Value1: Unknown; U/M: EA; Value: 10uF; TaMax_C: 125°C; SizeZ_mm: 1; SizeX_mm: 1.6; SizeY_mm: 0.8; Cap_Case: 0603; SizeArea_mm2: 1.28; Cap_F: 10µF; AEC Category: Q200
C102 C103 = CMP-0006607-2: CAP, CERM, 0.1 uF, 25 V, +/- 10%, X5R, 0402; Manufacturer: MuRata; TaMin_C: -55°C; Polarized: N; SizeAreaWB_mm2: 3; Value1: Unknown; U/M: EA; Value: 0.1uF; TaMax_C: 85°C; SizeZ_mm: 0.6; SizeX_mm: 1; SizeY_mm: 0.5; Cap_F: 100nF; AEC Category: Q200
R127 = CMP-0027453-1: RES, 1.00 k, 1%, 0.05 W, 0201; Manufacturer: Yageo America; Power_W: 50mW; TempCo: 200 ppm/C; Value_Code: 1k00; U/M: EA; Value: 1.00k; EIA_Code: E96; Res_ohm: 1k; SizeX_mm: 0.6; SizeY_mm: 0.3; SizeZ_mm: 0.26; Value2: 0.05W; SizeArea_mm2: 0.18; AEC Qualified: N; VDC_V: 25V; AEC Category: Q200
R128 = CMP-0027731-1: RES, 499, 1%, 0.05 W, 0201; Manufacturer: Yageo America; Power_W: 50mW; TempCo: 200 ppm/C; Value_Code: 499R; U/M: EA; Value: 499; EIA_Code: E96; SizeX_mm: 0.6; SizeY_mm: 0.3; SizeZ_mm: 0.26; Value2: 0.05W; SizeArea_mm2: 0.18; CompType: Resistor; AEC Qualified: N; VDC_V: 25V; AEC Category: Q200
R129 = CMP-0027094-3: RES, 2.0, 5%, 0.05 W, 0201; Manufacturer: Yageo America; Power_W: 50mW; TempCo: 350 ppm/C; Value_Code: 2R00; U/M: EA; Value: 2.0; EIA_Code: E24; Res_ohm: 2; SizeX_mm: 0.6; SizeY_mm: 0.3; SizeZ_mm: 0.26; Value2: 0.05W; SizeArea_mm2: 0.18; CompType: Resistor; AEC Qualified: N; VDC_V: 25V; AEC Category: Q200
R130 = CMP-0027008-4: as R135-R139 on sheet DC134_USB
R131 = CMP-0027940-1: RES, 9.76 k, 1%, 0.05 W, 0201; Manufacturer: Yageo America; Power_W: 50mW; TempCo: 200 ppm/C; Value_Code: 9k76; U/M: EA; Value: 9.76k; EIA_Code: E96; SizeX_mm: 0.6; SizeY_mm: 0.3; SizeZ_mm: 0.26; Value2: 0.05W; SizeArea_mm2: 0.18; CompType: Resistor; AEC Qualified: N; VDC_V: 25V; AEC Category: Q200
R132 = CMP-0027360-2: RES, 14.3 k, 1%, 0.05 W, 0201; Manufacturer: Yageo America; Power_W: 50mW; TempCo: 200 ppm/C; Value_Code: 14k3; U/M: EA; Value: 14.3k; EIA_Code: E96; SizeX_mm: 0.6; SizeY_mm: 0.3; SizeZ_mm: 0.26; Value2: 0.05W; SizeArea_mm2: 0.18; CompType: Resistor; AEC Qualified: N; VDC_V: 25V; AEC Category: Q200
R133 R134 = CMP-0022727-3: RES, 0.05, 1%, 0.1 W, AEC-Q200 Grade 1, 0603; Manufacturer: Panasonic; Power_W: 100mW; TempCo: 200 ppm/C; Value_Code: R050; Value: 0.05; EIA_Code: E96; SizeX_mm: 1.6; SizeY_mm: 0.8; SizeZ_mm: 1; Value2: 0.1W; SizeArea_mm2: 1.28; AEC Qualified: Y; AEC Category: Q200; SizeAreaWB_mm2: 4.68
U13 = CMP-0013237-2: Low Power, Precision, 105MHz, Voltage Feedback Op Amp, DBV0006A (SOT-6); Manufacturer: Texas Instruments; Alternate PartNumber: OPA837IDBVT; SizeX_mm: 2.8; SizeY_mm: 2.9; CompType: IC; SizeZ_mm: 1.45; SizeArea_mm2: 8.12; SizeAreaWB_mm2: 14.82; U/M: EA
U14 = CMP-0032542-1: 30 ppm / degC Drift, 3.9 uA Voltage Reference, -40 to 125 degC, 3-pin SC70 (DCK), Green (RoHS & no Sb/Br); Manufacturer: Texas Instruments; Temp Coeff(Max)(ppm/ degree C): 30; Iout/Iz(Max)(mA): 5; VI(Min)(V): 1.98; SubFamily: Series Voltage Reference; VO(V): 1.8; Rating: Catalog; Temp Coeff(Typ)(ppm/ degree C): 8; VI(Max)(V): 5.5
U15 U16 = CMP-0037979-1: High-Side Measurement, Bi-Directional Current / Power Monitor with I2C Interface, 2.7 to 5.5 V, -40 to 125 degC, 10-pin SOP (DGS10), Green (RoHS & no Sb/Br); Common Mode Range(Max)(V): 36; Vs(Min)(V): 2.7; SubFamily: Current Shunt Monitor; Small-Signal Bandwidth(Typ)(MHz): 0.007; CMRR(Min)(dB): 126; Gain(V/V): 1; Vs(Max)(V): 5.5; Rating: Catalog; Input Offset Drift (+/-)(Max)(uV/Degrees Celsius): 0.1; Quiescent Current (+/-)(Typ)(mA): 0.33; Common Mode Range(Min)(V): 0; Input Offset (+/-)(Max)(uV): 10

## Sheet DC134_FMC.SchDoc
size 431 x 279 mm; Date: Not shown in title block; ApprovedBy: Not shown in title block; CheckedBy: Not shown in title block; Author: Not shown in title block; CompanyName: Not shown in title block; Engineer: Not shown in title block; Organization: Not shown in title block; Address1: Not shown in title block; Address2: Not shown in title block; Address3: Not shown in title block; Address4: Not shown in title block; DocumentNumber: 8; Revision: Use project parameter SCH_Rev; SheetNumber: 8; SheetTotal: 9; PageSetup: Record=PageOptions¦CenterHorizontal=True¦CenterVertical=True¦PrintScale=1.00¦XCorrection=1.00¦YCorrection=1.00¦PrintKind=0¦BorderSize=5000000¦LeftOffset=0¦BottomOffset=0¦Orientation=2¦PaperLength=1000¦PaperWidth=1000¦Scale=100¦PaperSource=15¦PrintQuality=600¦MediaType=1¦DitherType=10¦PaperKind=Letter¦PrintScaleMode=1
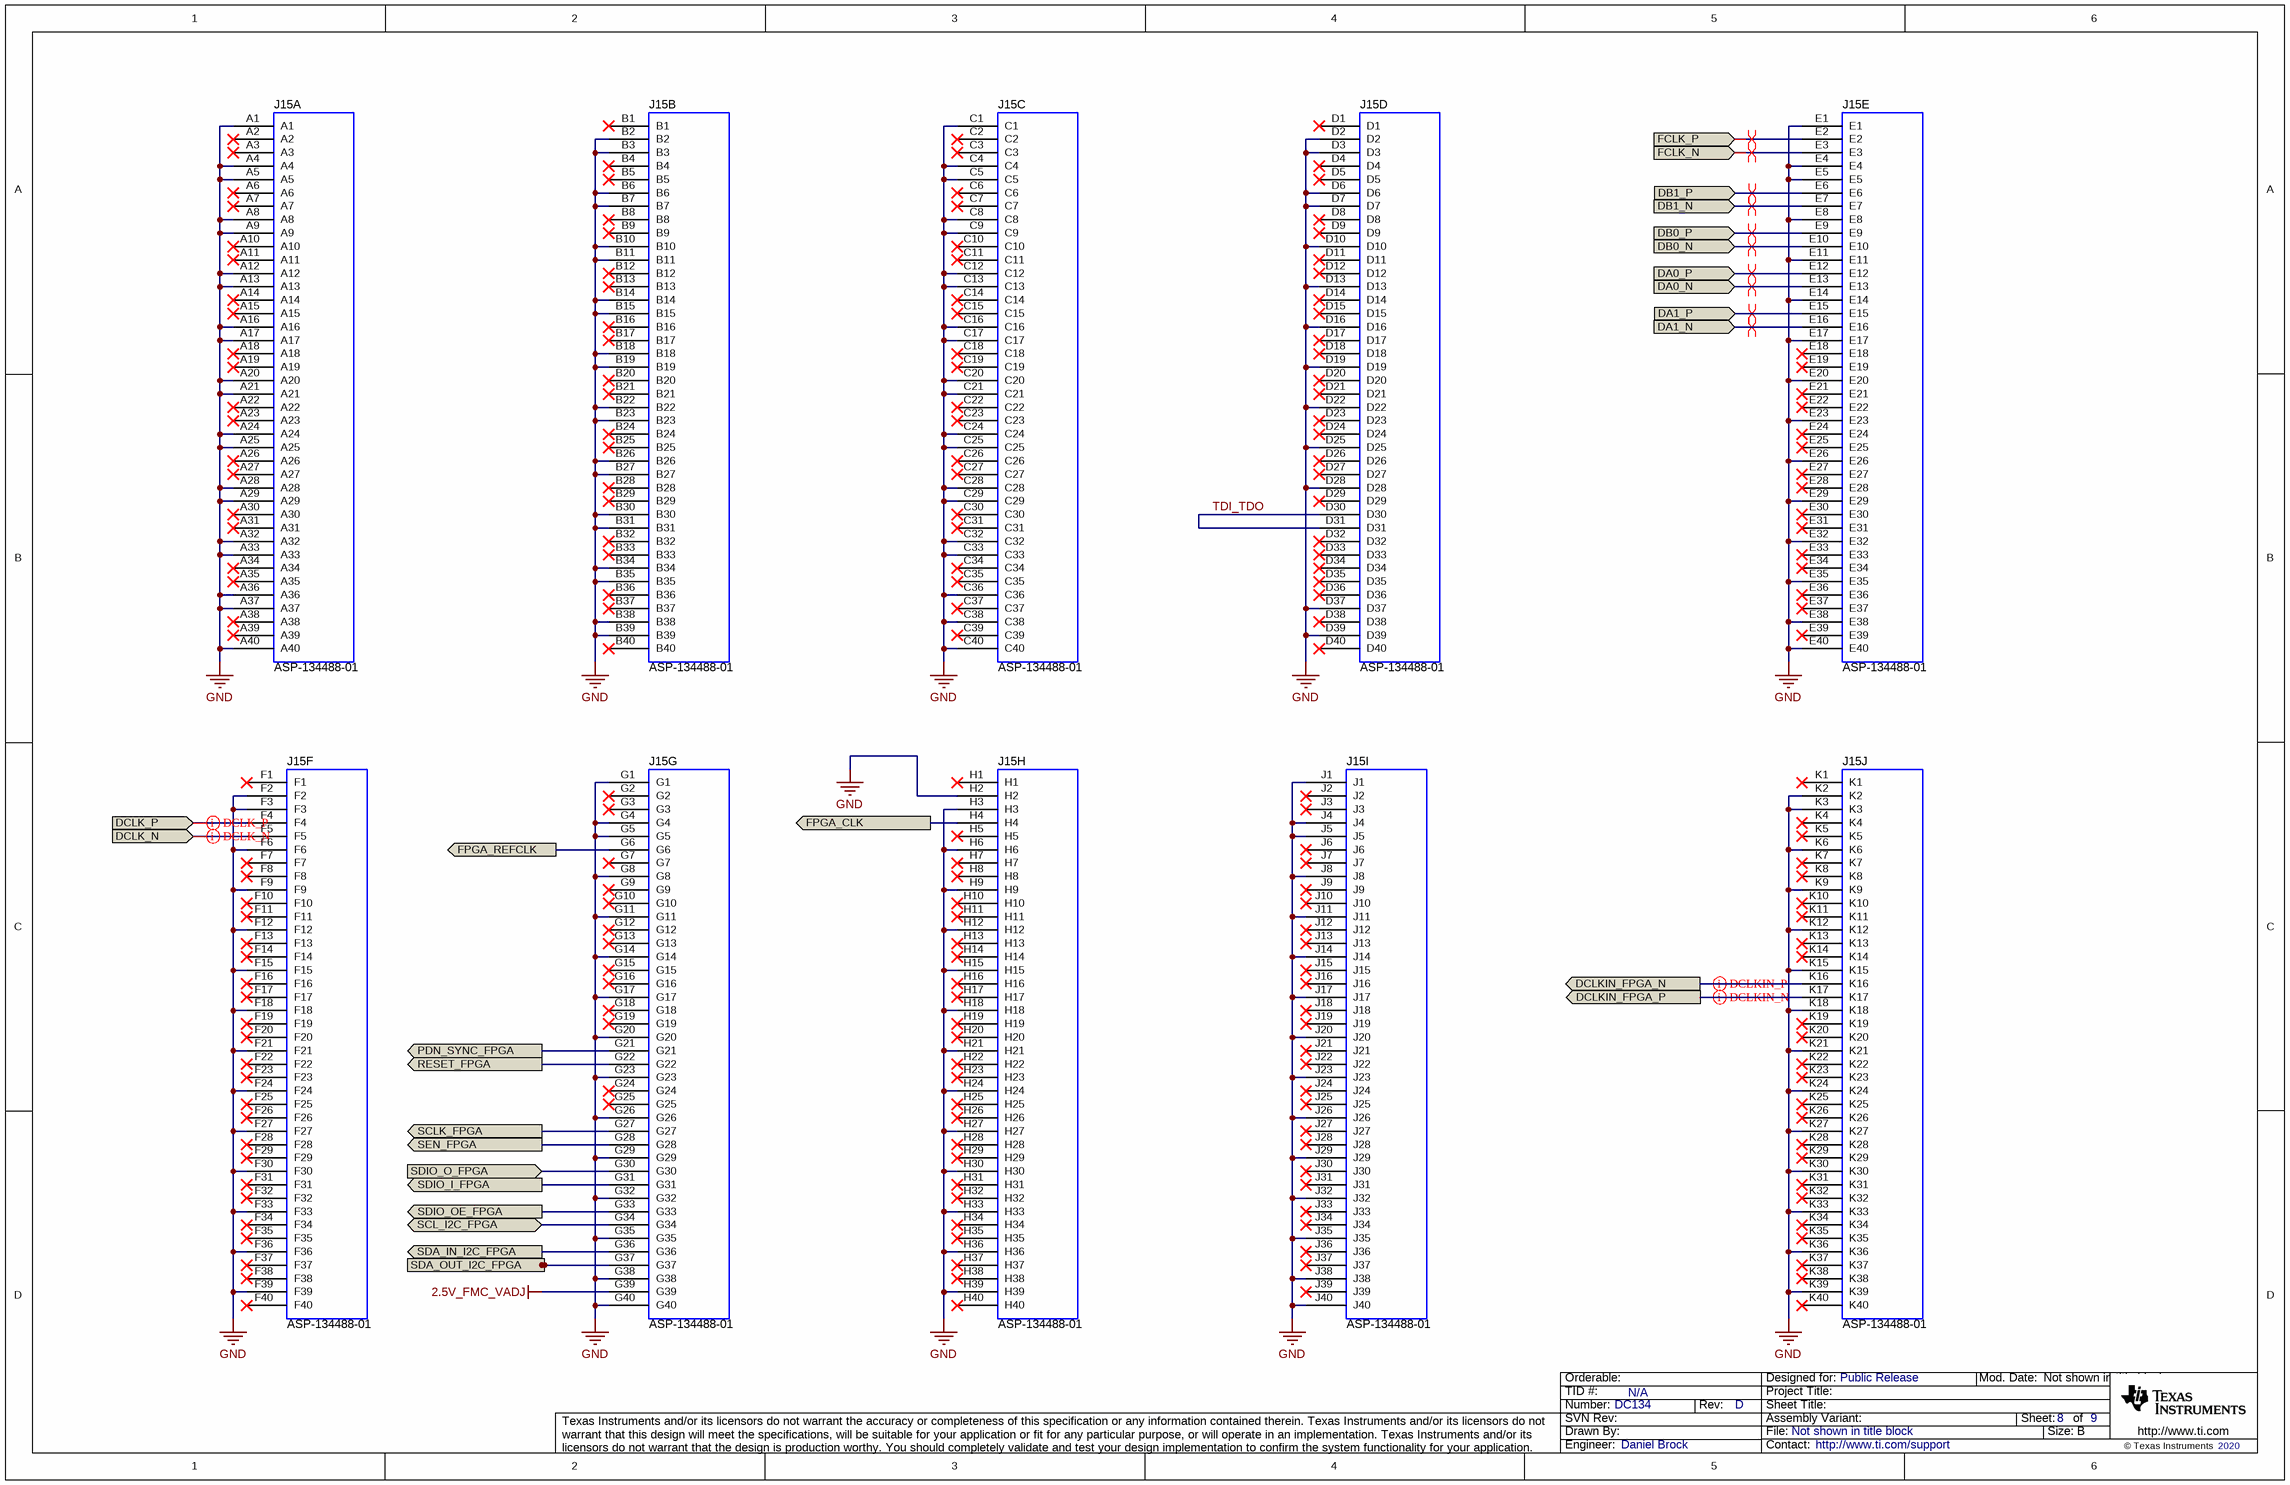
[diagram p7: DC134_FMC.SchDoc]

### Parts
J15  ASP-134488-01  [Samtec_ASP-134488-01]  (parts A,B,C,D,E,F,G,H,I,J of 10)

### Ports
DA0_N (in), DA0_P (in), DA1_N (in), DA1_P (in), DB0_N (in), DB0_P (in), DB1_N (in), DB1_P (in), DCLK_N (in), DCLK_P (in), DCLKIN_FPGA_N (out), DCLKIN_FPGA_P (out), FCLK_N (in), FCLK_P (in), FPGA_CLK (out), FPGA_REFCLK (out), PDN_SYNC_FPGA (out), RESET_FPGA (out), SCL_I2C_FPGA (bidir), SCLK_FPGA (out), SDA_IN_I2C_FPGA (out), SDA_OUT_I2C_FPGA (in), SDIO_I_FPGA (out), SDIO_O_FPGA (in), SDIO_OE_FPGA (out), SEN_FPGA (out)

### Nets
2.5V_FMC_VADJ: J15.G39
GND: J15.A1 J15.A4 J15.A5 J15.A8 J15.A9 J15.A12 J15.A13 J15.A16 J15.A17 J15.A20 J15.A21 J15.A24 J15.A25 J15.A28 J15.A29 J15.A32 J15.A33 J15.A36 J15.A37 J15.A40 J15.B2 J15.B3 J15.B6 J15.B7 J15.B10 J15.B11 J15.B14 J15.B15 J15.B18 J15.B19 J15.B22 J15.B23 J15.B26 J15.B27 J15.B30 J15.B31 J15.B34 J15.B35 J15.B38 J15.B39 J15.C1 J15.C4 J15.C5 J15.C8 J15.C9 J15.C12 J15.C13 J15.C16 J15.C17 J15.C20 J15.C21 J15.C24 J15.C25 J15.C28 J15.C29 J15.C32 J15.C33 J15.C36 J15.C38 J15.C40 J15.D2 J15.D3 J15.D6 J15.D7 J15.D10 J15.D13 J15.D16 J15.D19 J15.D22 J15.D25 J15.D28 J15.D37 J15.D39 J15.E1 J15.E4 J15.E5 J15.E8 J15.E11 J15.E14 J15.E17 J15.E20 J15.E23 J15.E26 J15.E29 J15.E32 J15.E35 J15.E38 J15.E40 J15.F2 J15.F3 J15.F6 J15.F9 J15.F12 J15.F15 J15.F18 J15.F21 J15.F24 J15.F27 J15.F30 J15.F33 J15.F36 J15.F39 J15.G1 J15.G4 J15.G5 J15.G8 J15.G11 J15.G14 J15.G17 J15.G20 J15.G23 J15.G26 J15.G29 J15.G32 J15.G35 J15.G38 J15.G40 J15.H2 J15.H3 J15.H6 J15.H9 J15.H12 J15.H15 J15.H18 J15.H21 J15.H24 J15.H27 J15.H30 J15.H33 J15.H36 J15.H39 J15.J1 J15.J4 J15.J5 J15.J8 J15.J11 J15.J14 J15.J17 J15.J20 J15.J23 J15.J26 J15.J29 J15.J32 J15.J35 J15.J38 J15.J40 J15.K2 J15.K3 J15.K6 J15.K9 J15.K12 J15.K15 J15.K18 J15.K21 J15.K24 J15.K27 J15.K30 J15.K33 J15.K36 J15.K39
DA0_N: J15.E13 ; port DA0_N
DA0_P: J15.E12 ; port DA0_P
DA1_N: J15.E16 ; port DA1_N
DA1_P: J15.E15 ; port DA1_P
DB0_N: J15.E10 ; port DB0_N
DB0_P: J15.E9 ; port DB0_P
DB1_N: J15.E7 ; port DB1_N
DB1_P: J15.E6 ; port DB1_P
DCLK_N: J15.F5 ; port DCLK_N
DCLK_P: J15.F4 ; port DCLK_P
DCLKIN_FPGA_N: J15.K16 ; port DCLKIN_FPGA_N
DCLKIN_FPGA_P: J15.K17 ; port DCLKIN_FPGA_P
FCLK_N: J15.E3 ; port FCLK_N
FCLK_P: J15.E2 ; port FCLK_P
FPGA_CLK: J15.H4 ; port FPGA_CLK
FPGA_REFCLK: J15.G6 ; port FPGA_REFCLK
PDN_SYNC_FPGA: J15.G21 ; port PDN_SYNC_FPGA
RESET_FPGA: J15.G22 ; port RESET_FPGA
SCL_I2C_FPGA: J15.G34 ; port SCL_I2C_FPGA
SCLK_FPGA: J15.G27 ; port SCLK_FPGA
SDA_IN_I2C_FPGA: J15.G36 ; port SDA_IN_I2C_FPGA
SDA_OUT_I2C_FPGA: J15.G37 ; port SDA_OUT_I2C_FPGA
SDIO_I_FPGA: J15.G31 ; port SDIO_I_FPGA
SDIO_O_FPGA: J15.G30 ; port SDIO_O_FPGA
SDIO_OE_FPGA: J15.G33 ; port SDIO_OE_FPGA
SEN_FPGA: J15.G28 ; port SEN_FPGA
TDI_TDO: J15.D30 J15.D31

Not connected (* = marked no-connect by the designer): J15 A2* A3* A6* A7* A10* A11* A14* A15* A18* A19* A22* A23* A26* A27* A30* A31* A34* A35* A38* A39* B1* B4* B5* B8* B9* B12* B13* B16* B17* B20* B21* B24* B25* B28* B29* B32* B33* B36* B37* B40* C2* C3* C6* C7* C10* C11* C14* C15* C18* C19* C22* C23* C26* C27* C30* C31* C34* C35* C37* C39* D1* D4* D5* D8* D9* D11* D12* D14* D15* D17* D18* D20* D21* D23* D24* D26* D27* D29* D32* D33* D34* D35* D36* D38* D40* E18* E19* E21* E22* E24* E25* E27* E28* E30* E31* E33* E34* E36* E37* E39* F1* F7* F8* F10* F11* F13* F14* F16* F17* F19* F20* F22* F23* F25* F26* F28* F29* F31* F32* F34* F35* F37* F38* F40* G2* G3* G7* G9* G10* G12* G13* G15* G16* G18* G19* G24* G25* H1* H5* H7* H8* H10* H11* H13* H14* H16* H17* H19* H20* H22* H23* H25* H26* H28* H29* H31* H32* H34* H35* H37* H38* H40* J2* J3* J6* J7* J9* J10* J12* J13* J15* J16* J18* J19* J21* J22* J24* J25* J27* J28* J30* J31* J33* J34* J36* J37* J39* K1* K4* K5* K7* K8* K10* K11* K13* K14* K19* K20* K22* K23* K25* K26* K28* K29* K31* K32* K34* K35* K37* K38* K40*

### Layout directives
differential pair: DA0_N, DA0_P, DA1_N, DA1_P, DB0_N, DB0_P, DB1_N, DB1_P, DCLK_N, DCLK_P, DCLKIN_FPGA_N, DCLKIN_FPGA_P, FCLK_N, FCLK_P

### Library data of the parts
J15 = CMP-0075635-1: Connector, 1.27mm, 40x10, Black, SMT; Manufacturer: Samtec; Pitch_mm: 1.27; Gender: Male; Cert_UL: Y; Green_REACh: Incomplete; CT: True; Green_Lifecycle: Not Set; Row_Count: 10; CompType: Terminal Block; CNHeader: False

## Sheet DC134_Hardware.SchDoc
size 431 x 279 mm; Date: Not shown in title block; ApprovedBy: Not shown in title block; CheckedBy: Not shown in title block; Author: Not shown in title block; CompanyName: Not shown in title block; Engineer: Not shown in title block; Organization: Not shown in title block; Address1: Not shown in title block; Address2: Not shown in title block; Address3: Not shown in title block; Address4: Not shown in title block; DocumentNumber: 9; Revision: Use project parameter SCH_Rev; SheetNumber: 9; SheetTotal: 9; PageSetup: Record=PageOptions¦CenterHorizontal=True¦CenterVertical=True¦PrintScale=1.00¦XCorrection=1.00¦YCorrection=1.00¦PrintKind=0¦BorderSize=5000000¦LeftOffset=0¦BottomOffset=0¦Orientation=2¦PaperLength=1000¦PaperWidth=1000¦Scale=100¦PaperSource=15¦PrintQuality=600¦MediaType=1¦DitherType=10¦PaperKind=Letter¦PrintScaleMode=1
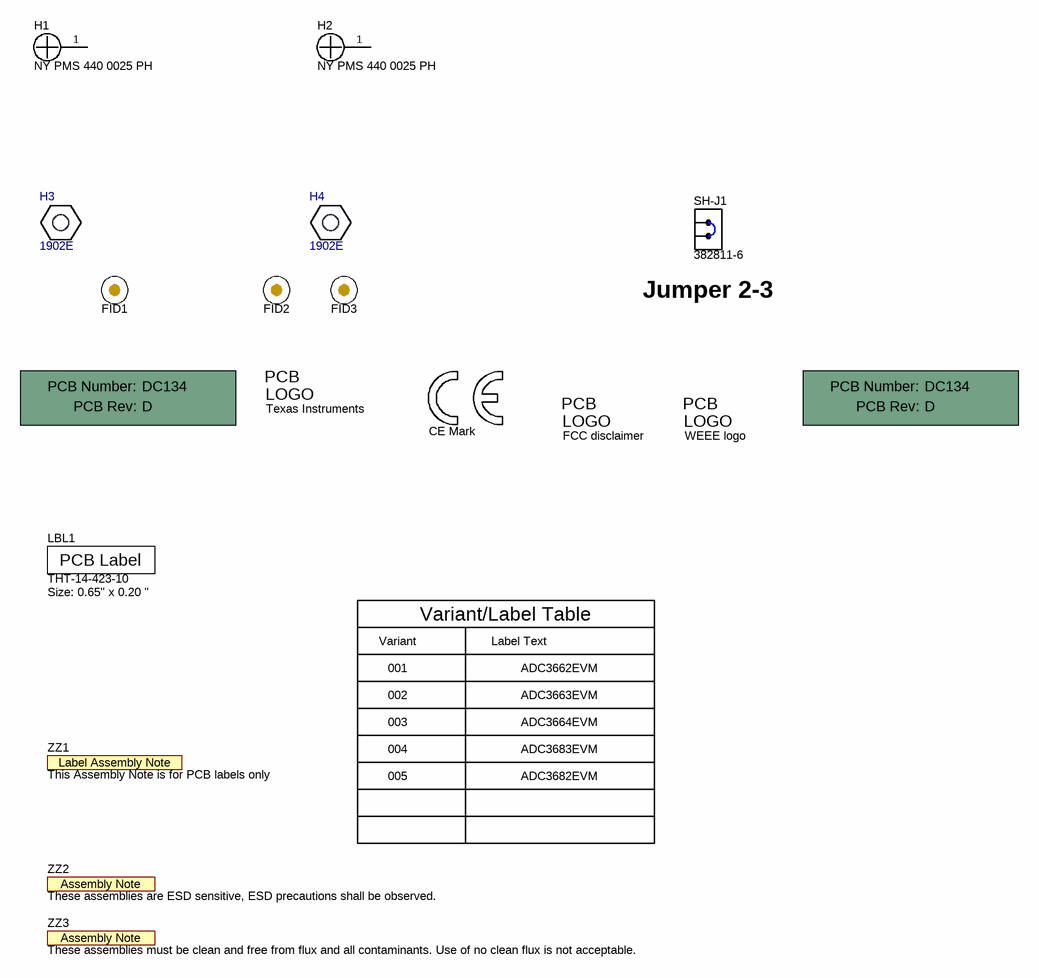
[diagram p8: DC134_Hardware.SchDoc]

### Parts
!PCB1  Printed Circuit Board  (value not drawn)  (mechanical)
!PCB2  Printed Circuit Board  (value not drawn)  (mechanical)
FID1  Fiducial  [Fiducial10-20]  (value not drawn)
FID2  Fiducial  [Fiducial10-20]  (value not drawn)
FID3  Fiducial  [Fiducial10-20]  (value not drawn)
H1  NY PMS 440 0025 PH  [NY PMS 440 0025 PH]
H2  NY PMS 440 0025 PH  [NY PMS 440 0025 PH]
H3  1902E  [Keystone_1902E]
H4  1902E  [Keystone_1902E]
LBL1  THT-14-423-10  Note: Size: 0.65" x 0.20 "  [Label_650x200]
Logo1  Texas Instruments  [TI_Stacked_Overlay_Small]  (no BOM)
Logo2  CE Mark  [CE_Mark_5mm]  (no BOM)
Logo3  FCC disclaimer  [FCC_disclaimer]  (no BOM)
Logo4  WEEE logo  [WEEE_Minimum]  (no BOM)
SH-J1  382811-6  (mechanical)
ZZ1  This Assembly Note is for PCB labels only  [AssemblyNoteLabel]  (no BOM)
ZZ2  These assemblies are ESD sensitive, ESD precautions shall be observed.  [AssemblyNote]  (no BOM)
ZZ3  These assemblies must be clean and free from flux and all contaminants. Use of no clean flux is not acceptable.  [AssemblyNote]  (no BOM)

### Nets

Not connected (* = marked no-connect by the designer): H1 1; H2 1

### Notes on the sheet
- (near SH-J1) Jumper 2-3
- Variant
- Variant/Label Table
- Label Text
- 001
- 002
- ADC3662EVM
- ADC3663EVM
- 003
- 004
- 005
- ADC3664EVM
- ADC3683EVM
- ADC3682EVM

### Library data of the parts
!PCB1 = CMP-0003618-2: Manufacturer: Any; PartNumber: DC134; CompType: PCB
!PCB2 = CMP-0003618-2: Printed Circuit Board, LVDS Interposer Card 35XX_L_INT; Manufacturer: Any; PartNumber: DC134; CompType: PCB
FID1-FID3 = CMP-0077181-1: Fiducial mark.  There is nothing to buy or mount.
H1 H2 = CMP-0003617-1: Machine Screw, Round, #4-40 x 1/4, Nylon, Philips panhead; Manufacturer: B&F Fastener Supply; CompType: Hardware
H3 H4 = CMP-0003611-1: Manufacturer: Keystone; CompType: Hardware
LBL1 = CMP-0003625-1: Thermal Transfer Printable Labels, 0.650" W x 0.200" H - 10,000 per roll; Manufacturer: Brady; CompType: Label
Logo1 = CMP-0074838-1: Texas Instrument Corporate Signature; SymbolCreator: a0412235; Lib Reference: TI_Logo; Library Reference: Logo
Logo2 = CMP-0074844-1: SymbolCreator: a0412235
Logo3 = CMP-0074847-1: FCC_disclaimer; Library Reference: Logo
Logo4 = CMP-0074769-1
SH-J1 = CMP-0003613-1: Shunt, 100mil, Gold plated, Black; Manufacturer: AMP; Value: 1x2
ZZ1 = CMP-0003616-3
ZZ2 = CMP-0077236-1
ZZ3 = CMP-0077237-1

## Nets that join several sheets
2.5V_FMC_VADJ: DC134_USB (R153.1 R174.1), DC134_FMC (J15.G39)
+3.3V: DC134_FDA (R85.2 R93.2 R102.2 R108.2), DC134_CLK (17 pins), DC134_USB (26 pins), DC134_Power (7 pins), DC134_Reference (11 pins)
-0.23V_CHA: DC134_FDA (8 pins), DC134_Power (C88.1 R123.2)
-0.23V_CHB: DC134_FDA (8 pins), DC134_Power (C90.1 R124.2)
AVDD: DC134_Device (11 pins), DC134_CLK (R31.2 Y1.4), DC134_Reference (R133.1 U15.8 U15.9)
AVDD+: DC134_Power (C75.1 C76.1 FB2.3), DC134_Reference (R133.2 U15.10)
GND: DC134_Device (26 pins), DC134_AIN (30 pins), DC134_FDA (24 pins), DC134_CLK (73 pins), DC134_USB (41 pins), DC134_Power (49 pins), DC134_Reference (15 pins), DC134_FMC (160 pins)
IOVDD: DC134_Device (6 pins), DC134_USB (C116.1 U18.1), DC134_Reference (R134.1 U16.8 U16.9)
IOVDD+: DC134_Power (C79.1 C80.1 FB3.3), DC134_Reference (R134.2 U16.10)
USB_+5Vin: DC134_USB (J17.1), DC134_Power (J16.3)
VCM_FDA_CHA: DC134_Device (R76.2), DC134_AIN (C5.2 R7.1 R8.2), DC134_FDA (C50.2 U6.9)
VCM_FDA_CHB: DC134_Device (R77.2), DC134_AIN (C13.2 R21.1 R22.2), DC134_FDA (C55.2 U7.9)
VREF: DC134_Device (C44.1 R79.2 U4.2), DC134_Reference (R130.2)
AIN_N: DC134_Device (U4.13), DC134_AIN (R5.2)
AIN_P: DC134_Device (U4.12), DC134_AIN (R12.2)
AMP_CHA_IN_N: DC134_AIN (R13.1), DC134_FDA (R88.1 R91.2 R92.2)
AMP_CHA_IN_P: DC134_AIN (R2.1), DC134_FDA (R82.1 R83.1 R86.1)
AMP_CHA_OUT_N: DC134_AIN (R14.1), DC134_FDA (C52.2 L12.2 R87.1)
AMP_CHA_OUT_P: DC134_AIN (R1.1), DC134_FDA (C52.1 L11.2 R87.2)
AMP_CHB_IN_N: DC134_AIN (R27.1), DC134_FDA (R105.1 R109.2 R110.2)
AMP_CHB_IN_P: DC134_AIN (R16.1), DC134_FDA (R99.1 R100.1 R103.1)
AMP_CHB_OUT_N: DC134_AIN (R28.1), DC134_FDA (C57.2 L14.2 R104.1)
AMP_CHB_OUT_P: DC134_AIN (R15.1), DC134_FDA (C57.1 L13.2 R104.2)
BIN_N: DC134_Device (U4.38), DC134_AIN (R26.2)
BIN_P: DC134_Device (U4.39), DC134_AIN (R19.2)
CLK_N: DC134_Device (U4.7), DC134_CLK (C26.2 R54.2)
CLK_P: DC134_Device (U4.6), DC134_CLK (C21.2 R30.2 R41.2 R46.2)
DA0_N: DC134_Device (U4.19), DC134_FMC (J15.E13)
DA0_P: DC134_Device (U4.20), DC134_FMC (J15.E12)
DA1_N: DC134_Device (U4.17), DC134_FMC (J15.E16)
DA1_P: DC134_Device (U4.18), DC134_FMC (J15.E15)
DB0_N: DC134_Device (U4.32), DC134_FMC (J15.E10)
DB0_P: DC134_Device (U4.31), DC134_FMC (J15.E9)
DB1_N: DC134_Device (U4.34), DC134_FMC (J15.E7)
DB1_P: DC134_Device (U4.33), DC134_FMC (J15.E6)
DCLK_N: DC134_Device (U4.22), DC134_FMC (J15.F5)
DCLK_P: DC134_Device (U4.23), DC134_FMC (J15.F4)
DCLKIN_FPGA_N: DC134_CLK (U2.9), DC134_FMC (J15.K16)
DCLKIN_FPGA_P: DC134_CLK (U2.10), DC134_FMC (J15.K17)
DCLKIN_N: DC134_Device (U4.24), DC134_CLK (U2.3)
DCLKIN_P: DC134_Device (U4.25), DC134_CLK (U2.2)
FCLK_N: DC134_Device (U4.29), DC134_FMC (J15.E3)
FCLK_P: DC134_Device (U4.28), DC134_FMC (J15.E2)
FPGA_CLK: DC134_CLK (R41.1), DC134_FMC (J15.H4)
FPGA_REFCLK: DC134_CLK (R29.2), DC134_FMC (J15.G6)
SCL_I2C: DC134_CLK (U3.12), DC134_USB (R156.1 R158.2 R168.2), DC134_Reference (U15.5 U16.5)
SCL_I2C_FPGA: DC134_USB (R165.2 R167.1), DC134_FMC (J15.G34)
SCLK: DC134_Device (U4.35), DC134_USB (U18.5)
SCLK_FPGA: DC134_USB (R135.1), DC134_FMC (J15.G27)
SDA_I2C: DC134_CLK (U3.19), DC134_USB (R157.1 R163.2 U20.4 U23.2), DC134_Reference (U15.4 U16.4)
SDA_IN_I2C_FPGA: DC134_USB (R170.1), DC134_FMC (J15.G36)
SDA_OUT_I2C_FPGA: DC134_USB (R166.2 R169.1), DC134_FMC (J15.G37)
SDIO: DC134_Device (U4.10), DC134_USB (U18.3)
SDIO_I_FPGA: DC134_USB (R138.1), DC134_FMC (J15.G31)
SDIO_O_FPGA: DC134_USB (R139.1), DC134_FMC (J15.G30)
SDIO_OE_FPGA: DC134_USB (R137.1), DC134_FMC (J15.G33)
SEN: DC134_Device (U4.16), DC134_USB (U18.4)
SEN_FPGA: DC134_USB (R136.1), DC134_FMC (J15.G28)

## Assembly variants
001: not fitted C1 C8 C9 C16 C25 C30 C49 C53 C54 C58 J8 J10 J11 J12 L2 L5 L7 R1 R2 R13 R14 R15 R16 R27 R28 R29 R30 R31 R33 R35 R36 R38 R39 R41 R45 R46 R48 R49 R51 R52 R54 R56 R58 R62 R65 R66 R67 R68 R69 R70 R71 R72 R73 R74 R89 R95 R106 R112 R121 R122 R135 R136 R137 R138 R139 R145 R148 R151 R153 R167 R168 R169 R170 Y1 Y2 Y4
002: not fitted C1 C8 C9 C16 C25 C30 C49 C53 C54 C58 J8 J10 J11 J12 L2 L5 L7 R1 R2 R13 R14 R15 R16 R27 R28 R29 R30 R31 R33 R35 R36 R38 R39 R41 R45 R46 R48 R49 R51 R52 R54 R56 R58 R62 R65 R66 R67 R68 R69 R70 R71 R72 R73 R74 R89 R95 R106 R112 R121 R122 R135 R136 R137 R138 R139 R145 R148 R151 R153 R167 R168 R169 R170 Y1 Y2 Y4
003: not fitted C1 C8 C9 C16 C25 C30 C49 C53 C54 C58 J8 J10 J11 J12 L2 L5 L7 R1 R2 R13 R14 R15 R16 R27 R28 R29 R30 R31 R33 R35 R36 R38 R39 R41 R45 R46 R48 R49 R51 R52 R54 R56 R58 R62 R65 R66 R67 R68 R69 R70 R71 R72 R73 R74 R89 R95 R106 R112 R121 R122 R135 R136 R137 R138 R139 R145 R148 R151 R153 R167 R168 R169 R170 Y1 Y2 Y4
004: not fitted C1 C8 C9 C16 C25 C30 C49 C53 C54 C58 J8 J10 J11 J12 L2 L5 L7 R1 R2 R13 R14 R15 R16 R27 R28 R29 R30 R31 R33 R35 R36 R38 R39 R41 R45 R46 R48 R49 R51 R52 R54 R56 R58 R62 R65 R66 R67 R68 R69 R70 R71 R72 R73 R74 R89 R95 R106 R112 R121 R122 R135 R136 R137 R138 R139 R145 R148 R151 R153 R167 R168 R169 R170 R? Y1 Y2 Y4
005: not fitted C1 C8 C9 C16 C25 C30 C49 C53 C54 C58 J8 J10 J11 J12 L2 L5 L7 R1 R2 R13 R14 R15 R16 R27 R28 R29 R30 R31 R33 R35 R36 R38 R39 R41 R45 R46 R48 R49 R51 R52 R54 R56 R58 R62 R65 R66 R67 R68 R69 R70 R71 R72 R73 R74 R89 R95 R106 R112 R121 R122 R135 R136 R137 R138 R139 R145 R148 R151 R153 R167 R168 R169 R170 Y1 Y2 Y4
